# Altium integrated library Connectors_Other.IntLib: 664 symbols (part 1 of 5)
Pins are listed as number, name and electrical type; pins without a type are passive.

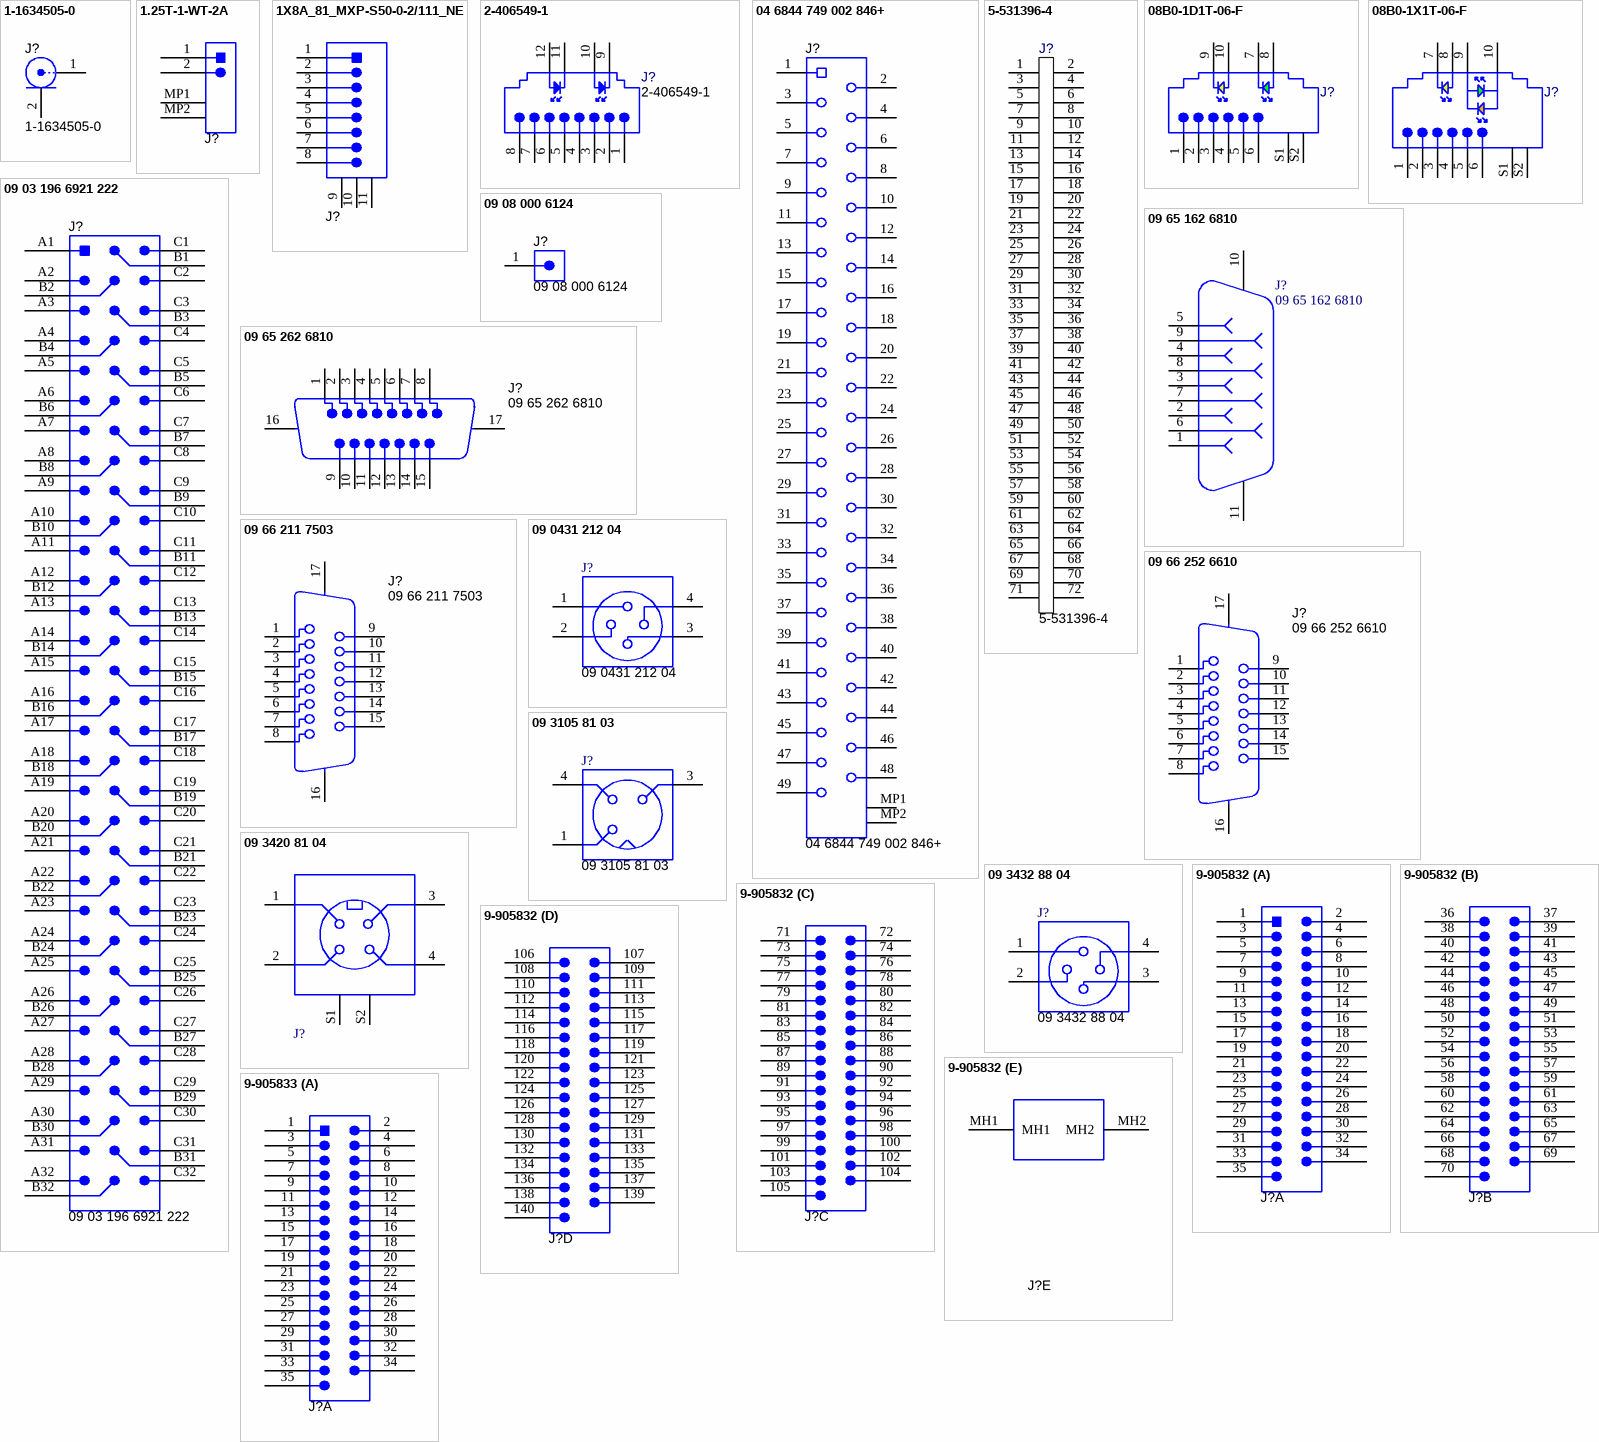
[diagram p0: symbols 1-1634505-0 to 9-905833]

## 1-1634505-0
designator J?
Conn Socket BNC straight 50 ohm PCB mount; Manufacturer: AMP; SymbolCreator: a0412235; Note: STEP model shows options mounting posts
footprint 1-1634505-0
pins: 1, 2

## 1.25T-1-WT-2A
designator J?  (value not drawn)
Header(shrouded), 1.25mm, 2x1, R/A, SMD; Manufacturer: Jhejiang Jinda Electronics; SymbolCreator: Altium; Pitch_mm: 1.25; Gender: Male; Shrouded: Y; Row_Count: 1; ContactFinish: Phosphor bronze; Voltage_V: 125
footprint Jinda_1_25T-1-WT-2A
pins: 1, 2, MP1, MP2

## 1X8A_81_MXP-S50-0-2/111_NE
designator J?  (value not drawn)
Straight PCB plug Pin-in-hole/SMT; Manufacturer: Huber+Suhner; SymbolCreator: a0411947; Green_Lifecycle: Not Set; Green_REACh: Incomplete
footprint H+S_1x8A_81_MXP-S50-0-2_111N
pins: 1, 2, 3, 4, 5, 6, 7, 8, 9, 10, 11

## 2-406549-1
designator J?
RJ45, Right Angle, Yellow/Green LED, tab up; Manufacturer: AMP; SymbolCreator: codlsc
footprint 2-406549-1
pins: 1, 2, 3, 4, 5, 6, 7, 8, 9 K1, 10 A1, 11 K2, 12 A2

## 04 6844 749 002 846+
designator J?
FPC Connector, 0.3mm, 49 Pos, R/A, SMT; Manufacturer: Kyocera; SymbolCreator: Altium; CompType: FFC or FPC; Pitch_mm: 0.3; Gender: Female; Row_Count: 1; Current_A: 0.2; Voltage_V: 50
footprint Kyocera_04_6844_749_002_846+
pins: 1, 2, 3, 4, 5, 6, 7, 8, 9, 10, 11, 12, 13, 14, 15, 16, 17, 18, 19, 20, 21, 22, 23, 24, 25, 26, 27, 28, 29, 30, 31, 32, 33, 34, 35, 36, 37, 38, 39, 40, 41, 42, 43, 44, 45, 46, 47, 48, 49, MP1, MP2

## 5-531396-4
designator J?
Right Angle ZIF connector - OBSOLETE; Manufacturer: AMP; SymbolCreator: codlsc; U/M: EA
footprint 5-531396-4
pins: 1, 2, 3, 4, 5, 6, 7, 8, 9, 10, 11, 12, 13, 14, 15, 16, 17, 18, 19, 20, 21, 22, 23, 24, 25, 26, 27, 28, 29, 30, 31, 32, 33, 34, 35, 36, 37, 38, 39, 40, 41, 42, 43, 44, 45, 46, 47, 48, 49, 50, 51, 52, 53, 54, 55, 56, 57, 58, 59, 60, 61, 62, 63, 64, 65, 66, 67, 68, 69, 70, 71, 72

## 08B0-1D1T-06-F
designator J?  (value not drawn)
Connector, RJ45, R/A, TH; Manufacturer: Bel Fuse; SymbolCreator: Altium; Pitch_mm: 2.03; Gender: Female; Row_Count: 2; RowSpacing_mm: 2.47; ContactFinish: Gold; Cert_UL: Y
footprint Bel_08B0-1D1T-06-F
pins: 1, 2, 3, 4, 5, 6, 7 K1, 8 A1, 9 K2, 10 A2, S1 SHIELD1, S2 SHIELD2

## 08B0-1X1T-06-F
designator J?  (value not drawn)
Connector, RJ45, R/A, TH; Manufacturer: Bel Fuse; SymbolCreator: Altium; Pitch_mm: 2.03; Gender: Female; Row_Count: 2; RowSpacing_mm: 2.47; ContactFinish: Gold; Cert_UL: Y
footprint Bel_08B0-1X1T-06-F
pins: 1, 2, 3, 4, 5, 6, 7 K1, 8 A1, 9 K2, 10 A2, S1 SHIELD1, S2 SHIELD2

## 09 03 196 6921 222
designator J?
Header, 2.54mm, 32x3, R/A, TH; Manufacturer: Harting; SymbolCreator: Altium; Pitch_mm: 2.54; Gender: Male; Shrouded: Y; Row_Count: 3
footprint Harting_09_03_196_6921_222
pins: A1, A2, A3 A2, A4 A3, A5 A3, A6 A4, A7 A4, A8 A5, A9 A5, A10 A6, A11 A6, A12 A7, A13 A7, A14 A8, A15 A8, A16 A9, A17 A9, A18 A10, A19 A10, A20 A11, A21 A11, A22 A12, A23 A12, A24 A13, A25 A13, A26 A14, A27 A14, A28 A15, A29 A15, A30 A16, A31 A16, A32 A17, B1, B2, B3 B2, B4 B3, B5 B3, B6 B4, B7 B4, B8 B5, B9 B5, B10 B6, B11 B6, B12 B7, B13 B7, B14 B8, B15 B8, B16 B9, B17 B9, B18 B10, B19 B10, B20 B11, B21 B11, B22 B12, B23 B12, B24 B13, B25 B13, B26 B14, B27 B14, B28 B15, B29 B15, B30 B16, B31 B16, B32 B17, C1, C2, C3 C2, C4 C3, C5 C3, C6 C4, C7 C4, C8 C5, C9 C5, C10 C6, C11 C6, C12 C7, C13 C7, C14 C8, C15 C8, C16 C9, C17 C9, C18 C10, C19 C10, C20 C11, C21 C11, C22 C12, C23 C12, C24 C13, C25 C13, C26 C14, C27 C14, C28 C15, C29 C15, C30 C16, C31 C16, C32 C17

## 09 08 000 6124
designator J?
Power Connector, 8AWG, SILVER W/PIN, TH; Manufacturer: Harting; SymbolCreator: a0412235
footprint Han-FastLock_09080006124
pins: 1

## 09 65 162 6810
designator J?
D-Sub-9, 11Pos, Male, TH; Manufacturer: Harting; SymbolCreator: x0208326; CompType: D-Sub
footprint Harting_09 65 162 6810
pins: 1, 2, 3, 4, 5, 6, 7, 8, 9, 10, 11

## 09 65 262 6810
designator J?
D-Sub-15, 17Pos, TH; Manufacturer: Harting; SymbolCreator: x0208325; CompType: D-Sub; Gender: Male
footprint Harting_09 65 262 6810
pins: 1, 2, 3, 4, 5, 6, 7, 8, 9, 10, 11, 12, 13, 14, 15, 16 MH1, 17 MH2

## 09 66 211 7503
designator J?
D-Sub-15, 17Pos, TH; Manufacturer: Harting; SymbolCreator: x0208325; CompType: D-Sub; Gender: Female
footprint Harting_09 66 211 7503
pins: 1, 2, 3, 4, 5, 6, 7, 8, 9, 10, 11, 12, 13, 14, 15, 16 MH1, 17 MH2

## 09 66 252 6610
designator J?
D-Sub-15, 17Pos, TH; Manufacturer: Harting; SymbolCreator: x0208325; CompType: D-Sub; Gender: Female
footprint Harting_09 66 252 6610
pins: 1, 2, 3, 4, 5, 6, 7, 8, 9, 10, 11, 12, 13, 14, 15, 16 MH1, 17 MH2

## 09 0431 212 04
designator J?
M12 Socket, 4Pos, TH; Manufacturer: Binder-Connector; SymbolCreator: x0208325
footprint Binder_713_763
footprint Binder_713_763_Edge_ENGR-ONLY
pins: 1, 2  , 3  , 4  

## 09 3105 81 03
designator J?
M5 Socket, 3Pos, Edge Mount; Manufacturer: Binder-Connector; SymbolCreator: Altium
footprint Binder_707_Edge_ENGR-ONLY
pins: 1, 3, 4

## 09 3420 81 04
designator J?  (value not drawn)
M8 Socket, 4Pos, Gold, TH; Manufacturer: Binder-Connector; SymbolCreator: Altium; Gender: Female; Current_A: 4; Voltage_V: 60; Cert_UL: Y
footprint Binder_09_3420_81_04
pins: 1, 2  , 3, 4  , S1, S2

## 09 3432 88 04
designator J?
M12-A Socket, 4Pos, TH; Manufacturer: Binder-Connector; SymbolCreator: x0208325; Gender: Female; Row_Count: 2; ContactFinish: Gold; Current_A: 4; Voltage_V: 250
footprint Binder_09_3432_88_04
footprint Binder_09_3432_88_04_Edge_ENG
pins: 1, 2  , 3  , 4  

## 9-905832
designator J?  (value not drawn)
Header(shrouded), 1.27mm, 140 Pos, TH; Manufacturer: Joy Signal Technology; SymbolCreator: Altium; Pitch_mm: 2.54; Gender: Male; Shrouded: Y; Row_Count: 8; RowSpacing_mm: 1.27; Current_A: 1.7
footprint Joysignal_9-905832
part A pins: 1, 2, 3, 4, 5, 6, 7, 8, 9, 10, 11, 12, 13, 14, 15, 16, 17, 18, 19, 20, 21, 22, 23, 24, 25, 26, 27, 28, 29, 30, 31, 32, 33, 34, 35
part B pins: 36, 37, 38, 39, 40, 41, 42, 43, 44, 45, 46, 47, 48, 49, 50, 51, 52, 53, 54, 55, 56, 57, 58, 59, 60, 61, 62, 63, 64, 65, 66, 67, 68, 69, 70
part C pins: 71, 72, 73, 74, 75, 76, 77, 78, 79, 80, 81, 82, 83, 84, 85, 86, 87, 88, 89, 90, 91, 92, 93, 94, 95, 96, 97, 98, 99, 100, 101, 102, 103, 104, 105
part D pins: 106, 107, 108, 109, 110, 111, 112, 113, 114, 115, 116, 117, 118, 119, 120, 121, 122, 123, 124, 125, 126, 127, 128, 129, 130, 131, 132, 133, 134, 135, 136, 137, 138, 139, 140
part E pins: MH1, MH2

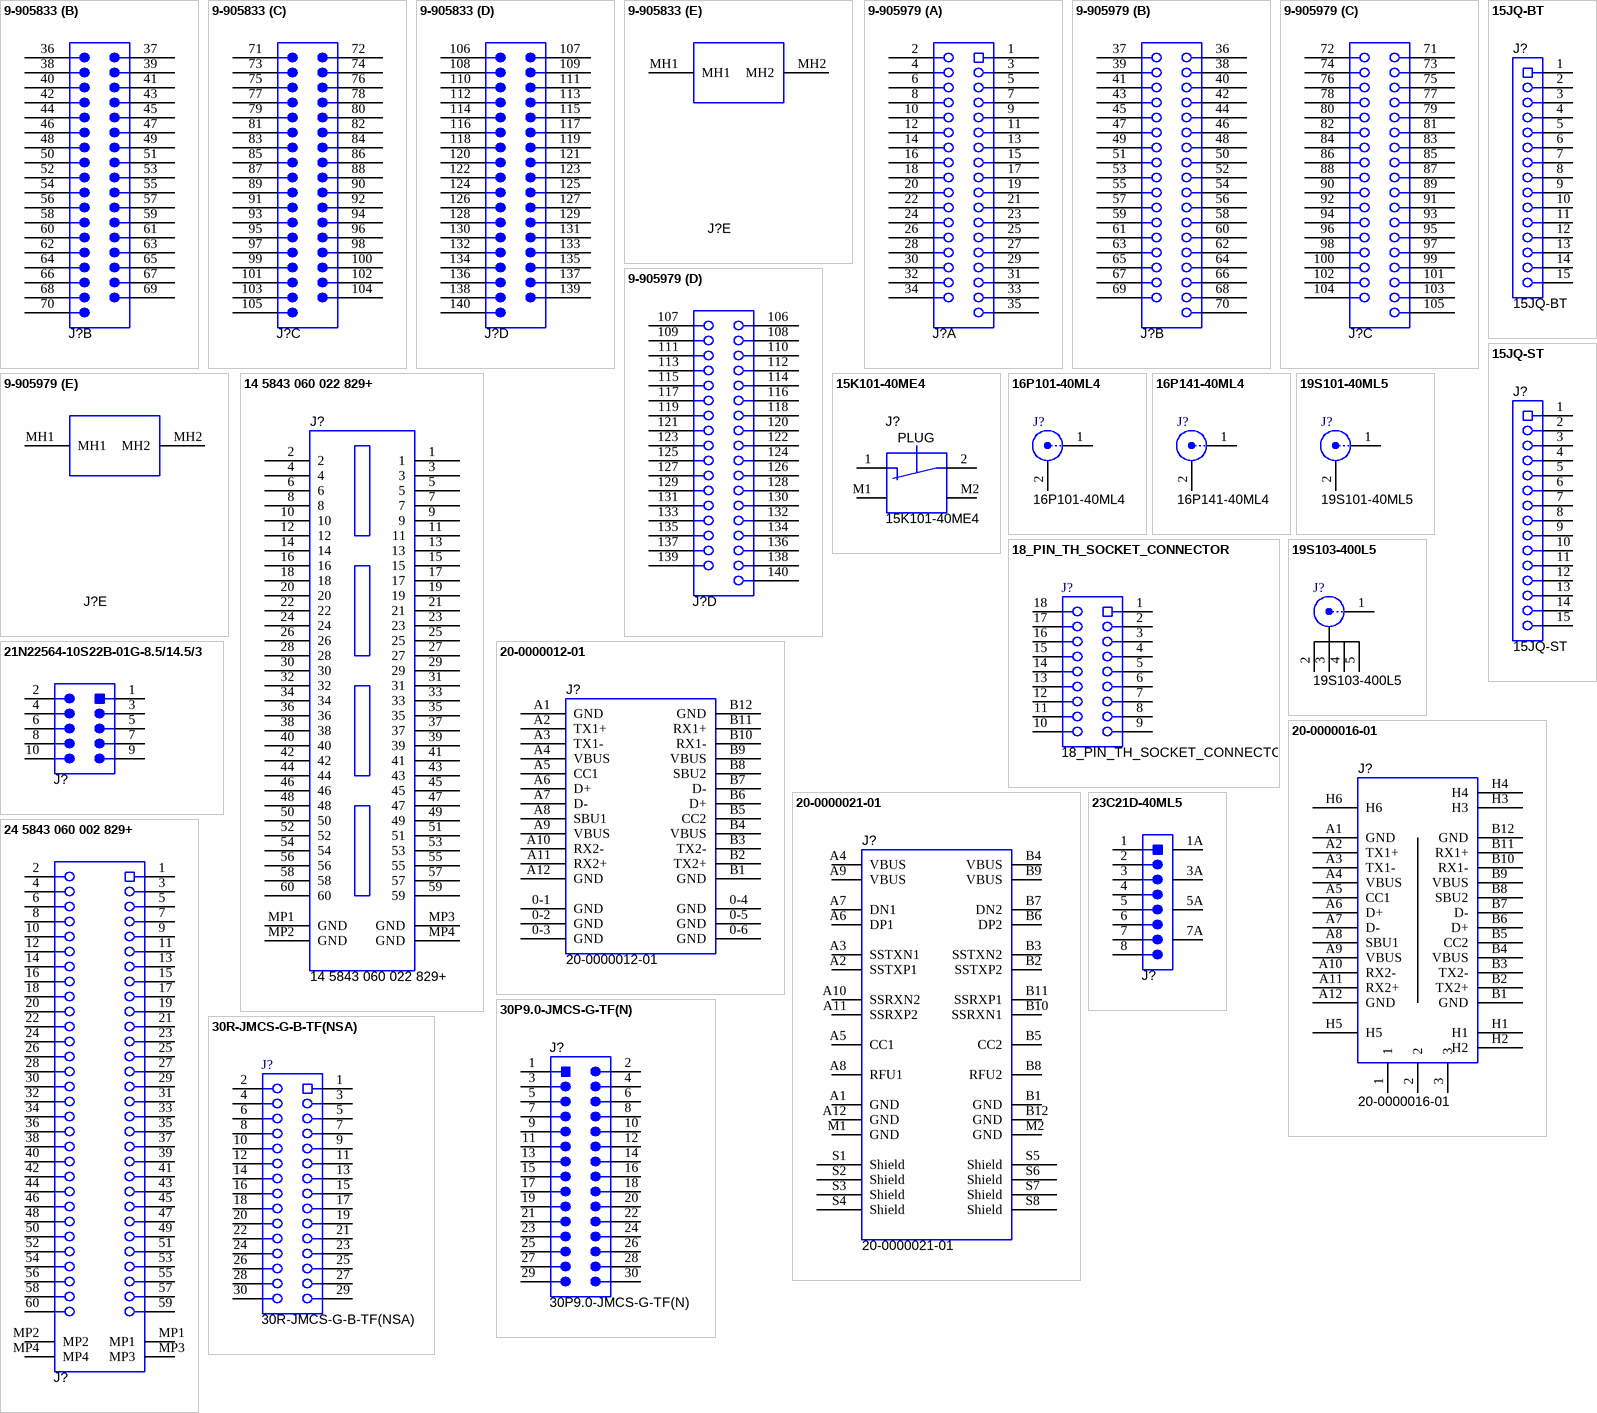
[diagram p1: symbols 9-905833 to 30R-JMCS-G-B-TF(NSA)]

## 9-905833
designator J?  (value not drawn)
Header(shrouded), 1.27mm, 140 Pos, R/A, TH; Manufacturer: Joy Signal Technology; SymbolCreator: Altium; Pitch_mm: 2.54; Gender: Male; Shrouded: Y; Row_Count: 8; RowSpacing_mm: 1.27; Current_A: 1.7
footprint Joysignal_9-905833
part A pins: 1, 2, 3, 4, 5, 6, 7, 8, 9, 10, 11, 12, 13, 14, 15, 16, 17, 18, 19, 20, 21, 22, 23, 24, 25, 26, 27, 28, 29, 30, 31, 32, 33, 34, 35
part B pins: 36, 37, 38, 39, 40, 41, 42, 43, 44, 45, 46, 47, 48, 49, 50, 51, 52, 53, 54, 55, 56, 57, 58, 59, 60, 61, 62, 63, 64, 65, 66, 67, 68, 69, 70
part C pins: 71, 72, 73, 74, 75, 76, 77, 78, 79, 80, 81, 82, 83, 84, 85, 86, 87, 88, 89, 90, 91, 92, 93, 94, 95, 96, 97, 98, 99, 100, 101, 102, 103, 104, 105
part D pins: 106, 107, 108, 109, 110, 111, 112, 113, 114, 115, 116, 117, 118, 119, 120, 121, 122, 123, 124, 125, 126, 127, 128, 129, 130, 131, 132, 133, 134, 135, 136, 137, 138, 139, 140
part E pins: MH1, MH2

## 9-905979
designator J?  (value not drawn)
Receptacle, 1.27mm, 140 Pos, R/A, TH; Manufacturer: Joy Signal Technology; SymbolCreator: Altium; Pitch_mm: 2.54; Gender: Female; Row_Count: 8; RowSpacing_mm: 1.27; Current_A: 1.7
footprint Joysignal_9-905979
part A pins: 1, 2, 3, 4, 5, 6, 7, 8, 9, 10, 11, 12, 13, 14, 15, 16, 17, 18, 19, 20, 21, 22, 23, 24, 25, 26, 27, 28, 29, 30, 31, 32, 33, 34, 35
part B pins: 36, 37, 38, 39, 40, 41, 42, 43, 44, 45, 46, 47, 48, 49, 50, 51, 52, 53, 54, 55, 56, 57, 58, 59, 60, 61, 62, 63, 64, 65, 66, 67, 68, 69, 70
part C pins: 71, 72, 73, 74, 75, 76, 77, 78, 79, 80, 81, 82, 83, 84, 85, 86, 87, 88, 89, 90, 91, 92, 93, 94, 95, 96, 97, 98, 99, 100, 101, 102, 103, 104, 105
part D pins: 106, 107, 108, 109, 110, 111, 112, 113, 114, 115, 116, 117, 118, 119, 120, 121, 122, 123, 124, 125, 126, 127, 128, 129, 130, 131, 132, 133, 134, 135, 136, 137, 138, 139, 140
part E pins: MH1, MH2

## 14 5843 060 022 829+
designator J?
Header, 0.35mm, 30x2, SMT; Manufacturer: Kyocera; SymbolCreator: Altium; Pitch_mm: 0.35; Gender: Male; Row_Count: 2; Current_A: 0.3; Voltage_V: 60
footprint Kyocera_14_5843_060_022_829+
pins: 1, 2, 3, 4, 5, 6, 7, 8, 9, 10, 11, 12, 13, 14, 15, 16, 17, 18, 19, 20, 21, 22, 23, 24, 25, 26, 27, 28, 29, 30, 31, 32, 33, 34, 35, 36, 37, 38, 39, 40, 41, 42, 43, 44, 45, 46, 47, 48, 49, 50, 51, 52, 53, 54, 55, 56, 57, 58, 59, 60, MP1 GND, MP2 GND, MP3 GND, MP4 GND
1 alternate drawing of the same symbol

## 15JQ-BT
designator J?
Receptacle, 2.5 mm, 15x1, TH; Manufacturer: JST Manufacturing; SymbolCreator: Altium
footprint JST_15JQ-BT
pins: 1, 2, 3, 4, 5, 6, 7, 8, 9, 10, 11, 12, 13, 14, 15

## 15JQ-ST
designator J?
Receptacle, 2.5 mm, 15x1, R/A, TH; Manufacturer: JST Manufacturing; SymbolCreator: Altium
footprint JST_15JQ-ST
pins: 1, 2, 3, 4, 5, 6, 7, 8, 9, 10, 11, 12, 13, 14, 15

## 15K101-40ME4
designator J?
RF Test Switch, SMD; Manufacturer: Rosenberger; SymbolCreator: x0208326
footprint Rosenberger_15K101-40ME4
pins: 1 "NC", 2 (power) "COM", M1, M2

## 16P101-40ML4
designator J?
FMC, Straight Jack, SMT; Manufacturer: Rosenberger; SymbolCreator: a0799628
footprint Rosenberger_16P101-40ML4
footprint Rosenberger_16P101-40ML4_NO-VIAS
pins: 1, 2

## 16P141-40ML4
designator J?
FMC, Straight Jack, SMT; Manufacturer: Rosenberger; SymbolCreator: a0799628
footprint Rosenberger_16P141-40ML4
footprint Rosenberger_16P141-40ML4_NO-VIAS
pins: 1, 2

## 18_PIN_TH_SOCKET_CONNECTOR
designator J?
18_PIN_TH_SOCKET_CONNECTOR, TH; Manufacturer: Texas Instruments; SymbolVersion: 20150930; SymbolCreator: Altium
footprint TI_18_PIN_TH_SOCKET_CONNECTOR
pins: 1, 2, 3, 4, 5, 6, 7, 8, 9, 10, 11, 12, 13, 14, 15, 16, 17, 18

## 19S101-40ML5
designator J?
Connector, RF 50 Ohms, SMT; Manufacturer: Rosenberger; SymbolCreator: a0799628
footprint 19S101_40ML5
pins: 1, 2

## 19S103-400L5
designator J?
Straight Plug, 50 Ohms, Gold, TH; Manufacturer: Rosenberger; SymbolCreator: a0799628; Gender: Male; Shrouded: N; Current_A: 1.2; Voltage_V: 335
footprint Rosenberger_19S103-400L5
pins: 1, 2, 3, 4, 5

## 20-0000012-01
designator J?
Connector, Plug, USB Type C, Edge Mount; Manufacturer: Lintes Technology; SymbolCreator: Altium; Gender: Female
footprint Lintes_20-0000012-01
pins: 0-1 GND, 0-2 GND, 0-3 GND, 0-4 GND, 0-5 GND, 0-6 GND, A1 GND, A2 TX1+, A3 TX1-, A4 VBUS, A5 CC1, A6 D+, A7 D-, A8 SBU1, A9 VBUS, A10 RX2-, A11 RX2+, A12 GND, B1 GND, B2 TX2+, B3 TX2-, B4 VBUS, B5 CC2, B6 D+, B7 D-, B8 SBU2, B9 VBUS, B10 RX1-, B11 RX1+, B12 GND

## 20-0000016-01
designator J?
Connector, Receptacle, USB Type C, R/A, SMT; Manufacturer: Lintes Technology; SymbolCreator: Altium; Gender: Female; Green_Lifecycle: Not Set; Green_REACh: Incomplete
footprint Lintes_20-0000016-01
pins: 1, 2, 3, A1 GND, A2 TX1+, A3 TX1-, A4 VBUS, A5 CC1, A6 D+, A7 D-, A8 SBU1, A9 VBUS, A10 RX2-, A11 RX2+, A12 GND, B1 GND, B2 TX2+, B3 TX2-, B4 VBUS, B5 CC2, B6 D+, B7 D-, B8 SBU2, B9 VBUS, B10 RX1-, B11 RX1+, B12 GND, H1, H2, H3, H4, H5, H6

## 20-0000021-01
designator J?
Receptacle, USB Type C, 26 Position; Manufacturer: Lintes Technology; SymbolCreator: Altium; Gender: Female; ContactFinish: Gold; Current_A: 3; Voltage_V: 5; Cert_UL: Y
footprint Lintes_20-0000021-01
pins: A1 GND, A2 SSTXP1, A3 SSTXN1, A4 VBUS, A5 CC1, A6 DP1, A7 DN1, A8 RFU1, A9 VBUS, A10 SSRXN2, A11 SSRXP2, A12 GND, B1 GND, B2 SSTXP2, B3 SSTXN2, B4 VBUS, B5 CC2, B6 DP2, B7 DN2, B8 RFU2, B9 VBUS, B10 SSRXN1, B11 SSRXP1, B12 GND, M1 GND, M2 GND, S1 Shield, S2 Shield, S3 Shield, S4 Shield, S5 Shield, S6 Shield, S7 Shield, S8 Shield

## 21N22564-10S22B-01G-8.5/14.5/3
designator J?  (value not drawn)
Header, 2.54mm, 5x2, Gold, TH; Manufacturer: JVE Global; SymbolCreator: Altium; Pitch_mm: 2.54; Gender: Male; Shrouded: N; Row_Count: 2; Current_A: 3; Voltage_V: 230; Cert_UL: Y
footprint JVE_21N22564-10S22B-01G-85-145-3
pins: 1, 2, 3, 4, 5, 6, 7, 8, 9, 10

## 23C21D-40ML5
designator J?  (value not drawn)
Mini-Coax, 8-Channel Block Right Angle; Manufacturer: Rosenberger; SymbolCreator: x0208325
footprint Rosenberger_23C21D-40ML5
pins: 1, 1A, 2, 3, 3A, 4, 5, 5A, 6, 7, 7A, 8

## 24 5843 060 002 829+
designator J?  (value not drawn)
Receptacle, 0.35mm, 30x2, SMT; Manufacturer: Kyocera; SymbolCreator: Altium; Pitch_mm: 0.35; Gender: Female; Row_Count: 2; Current_A: 0.3; Voltage_V: 60
footprint Kyocera_24_5843_060_002_829+
pins: 1, 2, 3, 4, 5, 6, 7, 8, 9, 10, 11, 12, 13, 14, 15, 16, 17, 18, 19, 20, 21, 22, 23, 24, 25, 26, 27, 28, 29, 30, 31, 32, 33, 34, 35, 36, 37, 38, 39, 40, 41, 42, 43, 44, 45, 46, 47, 48, 49, 50, 51, 52, 53, 54, 55, 56, 57, 58, 59, 60, MP1, MP2, MP3, MP4

## 30P9.0-JMCS-G-TF(N)
designator J?
Plug, 0.5mm, 15x2, SMD; Manufacturer: JST Manufacturing; SymbolCreator: a0412235
footprint JST_30P9_0-JMCS-G-TF
pins: 1, 2, 3, 4, 5, 6, 7, 8, 9, 10, 11, 12, 13, 14, 15, 16, 17, 18, 19, 20, 21, 22, 23, 24, 25, 26, 27, 28, 29, 30

## 30R-JMCS-G-B-TF(NSA)
designator J?
Receptacle, 0.5mm, 15x2, SMD; Manufacturer: JST Manufacturing; SymbolCreator: a0412235
footprint JST_30R-JMCS-G-B-TF
pins: 1, 2, 3, 4, 5, 6, 7, 8, 9, 10, 11, 12, 13, 14, 15, 16, 17, 18, 19, 20, 21, 22, 23, 24, 25, 26, 27, 28, 29, 30

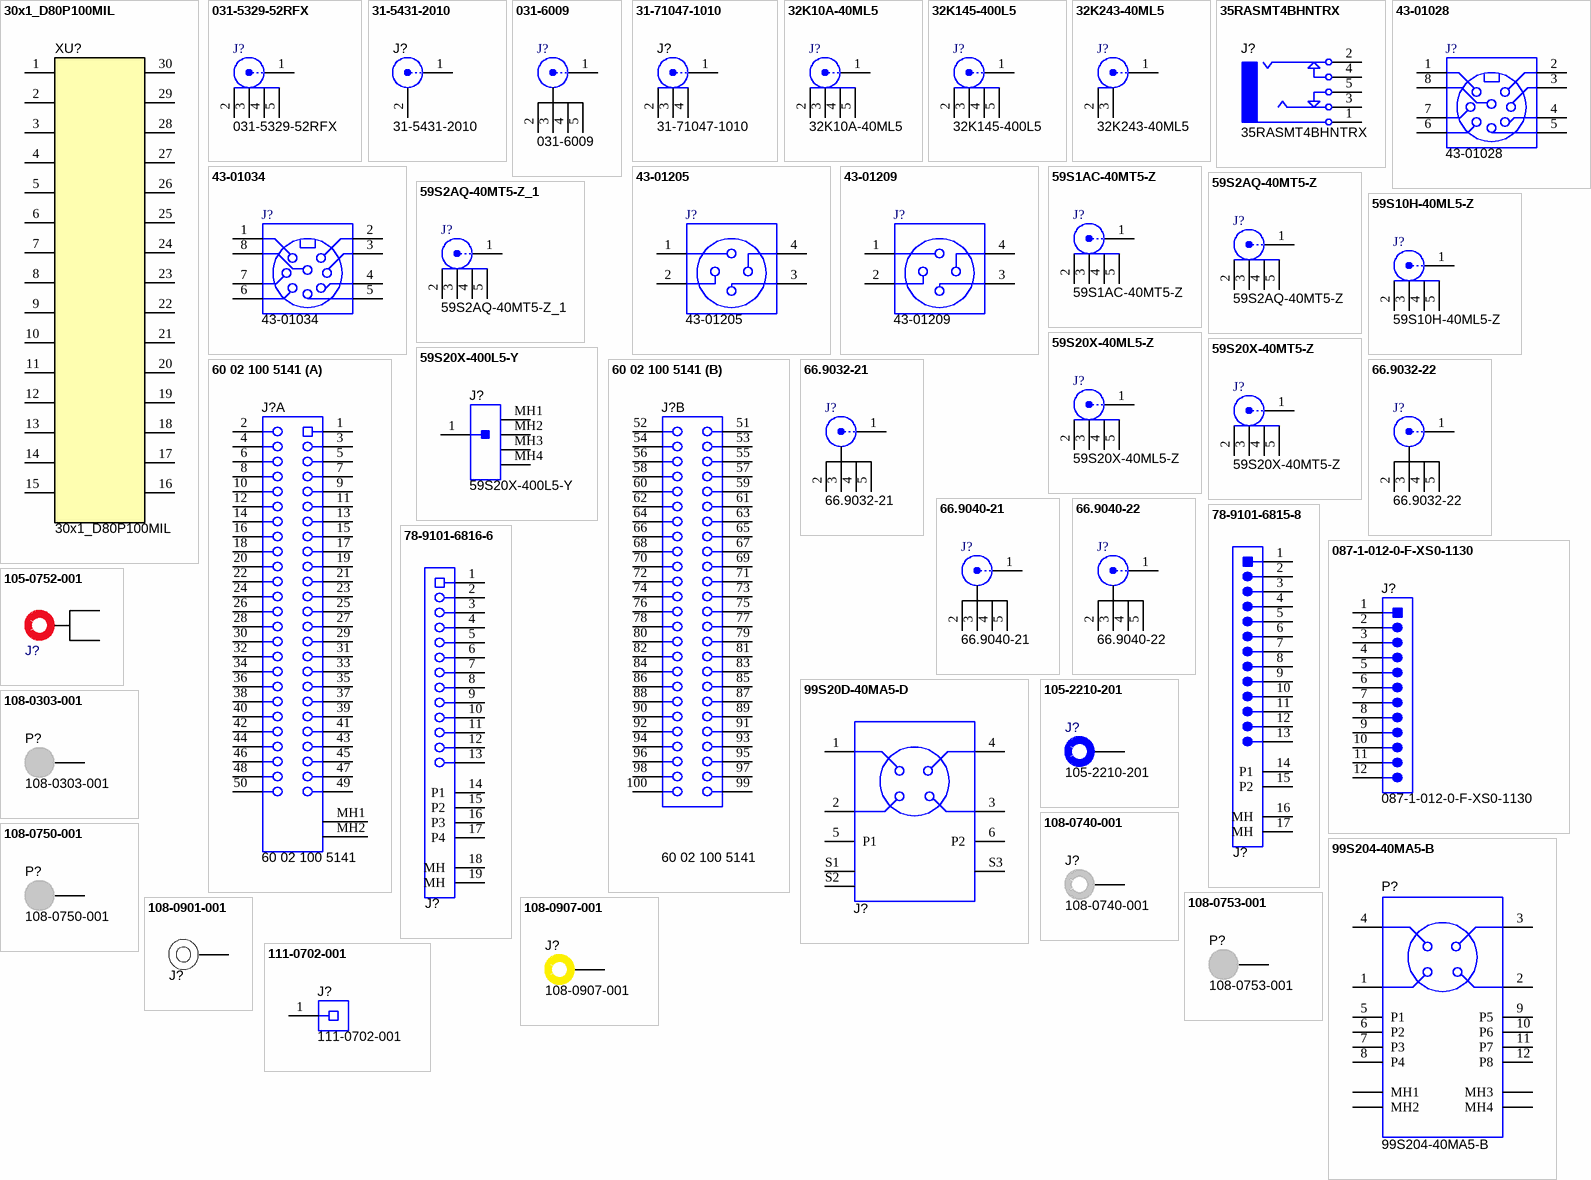
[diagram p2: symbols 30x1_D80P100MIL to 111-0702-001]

## 30x1_D80P100MIL
designator XU?
Footprint for pogo-pins, 100mil, 30x1, SMT; Manufacturer: Any; SymbolCreator: Altium; CompType: Connector; Pitch_mm: 2.54; Row_Count: 1
footprint TI-30x1_D80P100MIL
pins: 1, 2, 3, 4, 5, 6, 7, 8, 9, 10, 11, 12, 13, 14, 15, 16, 17, 18, 19, 20, 21, 22, 23, 24, 25, 26, 27, 28, 29, 30

## 031-5329-52RFX
designator J?
BNC Receptacle, 50 Ohm, TH; Manufacturer: Amphenol RF; SymbolCreator: X0208326; Gender: Female; ContactFinish: Gold; Voltage_V: 500
footprint Amphenol_031-5329-52RFX
pins: 1, 2, 3, 4, 5

## 31-5431-2010
designator J?
Connector, BNC Jack, 1 Position, R/A, TH; Manufacturer: Amphenol-Tuchel Electronics; SymbolCreator: Altium; Gender: Female; ContactFinish: Gold
footprint Amphenol_31-5431-2010
pins: 1, 2

## 031-6009
designator J?
75 Ohm BNC Edge Mount Receptacle, RF Connector, RoHS, SMT; Manufacturer: Amphenol RF; SymbolCreator: a0799628
footprint Amphenol_031-6009
pins: 1, 2, 3, 4, 5

## 31-71047-1010
designator J?
Connector, BNC, 75 ohm, Isolated, R/A, TH; Manufacturer: Amphenol RF; SymbolCreator: a0411947; Green_Lifecycle: Not Set; Green_REACh: Incomplete
footprint CONN_31-71047-1010
pins: 1, 2, 3, 4

## 32K10A-40ML5
designator J?
SMA, Straight Jack, SMT; Manufacturer: Rosenberger; SymbolCreator: X0208326
footprint Rosenberger_32K10A-40ML5
pins: 1, 2, 3, 4, 5

## 32K145-400L5
designator J?
SMA, Straight Jack, SMT; Manufacturer: Rosenberger; SymbolCreator: X0208326
footprint Rosenberger_32K145-400L5
footprint 32K145-400_FR4_130_ML_MS_SB
pins: 1, 2, 3, 4, 5

## 32K243-40ML5
designator J?
SMA JACK 50 OHM, R/A, SMT; Manufacturer: Rosenberger; SymbolCreator: a0412235; Gender: Male; ContactFinish: Gold; Voltage_V: 480; Green_Lifecycle: Not Set; Green_REACh: Incomplete
footprint Rosenberger_32K243-40ML5
pins: 1, 2, 3

## 35RASMT4BHNTRX
designator J?
Audio Jack, 3.5mm, Stereo, R/A, SMT; Manufacturer: Switchcraft; SymbolCreator: x0208326; CompType: Audio Connector
footprint Switchcraft_35RASM
pins: 1 SLEEVE, 2 RING, 3 TIP, 4 RING SWITCH, 5 TIP SWITCH

## 43-01028
designator J?
M12 Socket, 8Pos, TH; Manufacturer: Conec; SymbolCreator: x0208326
footprint Conec_43-01028
pins: 1, 2  , 3  , 4, 5, 6  , 7  , 8

## 43-01034
designator J?
M12 Socket, 8Pos, TH; Manufacturer: Conec; SymbolCreator: x0208326
footprint Conec_43-01034
pins: 1, 2  , 3  , 4, 5, 6  , 7  , 8

## 43-01205
designator J?
M12 Socket, Backmounting, 4Pos, Gold, R/A, TH; Manufacturer: Conec; SymbolCreator: x0208325
footprint Conec_43-01205
pins: 1, 2  , 3  , 4  

## 43-01209
designator J?
M12 Socket, Frontmounting, 4Pos, Gold, R/A, TH; Manufacturer: Conec; SymbolCreator: x0208325
footprint Conec_43-01209
pins: 1, 2  , 3  , 4  

## 59S1AC-40MT5-Z
designator J?
Connector, HF, 50 Ohm, TH; Manufacturer: Rosenberger; SymbolCreator: X0208326; Pitch_mm: 5.08; Gender: Male; ContactFinish: Tin; Current_A: 1; Voltage_V: 335
footprint Rosenberger_59S1AC-40MT5-Z
pins: 1, 2, 3, 4, 5

## 59S2AQ-40MT5-Z
designator J?
Connector. RF 50 Ohm R/A, TH; Manufacturer: Rosenberger; SymbolCreator: X0208326; CompType: Right Angle Plug
footprint Rosenberger_59S2AQ-40MT5
pins: 1, 2, 3, 4, 5

## 59S2AQ-40MT5-Z_1
designator J?
Connector, HF, 50 Ohm, TH; Manufacturer: Rosenberger; SymbolCreator: X0208326; Gender: Male; ContactFinish: Gold; Current_A: 1; Voltage_V: 335
footprint Rosenberger_59S2AQ-40MT5-Z_1
footprint Rosenberger_59S2AQ-40MT5-Z_1_Alternate
pins: 1, 2, 3, 4, 5

## 59S10H-40ML5-Z
designator J?
Connector, HF, 50 Ohm, TH; Manufacturer: Rosenberger; SymbolCreator: X0208326; Gender: Male; ContactFinish: Gold; Green_Lifecycle: Not Set; Green_REACh: Incomplete
footprint Rosenberger_59S10H-40ML5-Z
pins: 1, 2, 3, 4, 5

## 59S20X-40ML5-Z
designator J?
Connector, RF, 50 Ohm, R/A, TH; Manufacturer: Rosenberger; SymbolCreator: X0208326
footprint Rosenberger_59S20X-40ML5-Z
pins: 1, 2, 3, 4, 5

## 59S20X-40MT5-Z
designator J?
Connector. RF 50 Ohm R/A, TH; Manufacturer: Rosenberger; SymbolCreator: X0208326
footprint Rosenberger_59S20X-40MT5-Z
pins: 1, 2, 3, 4, 5

## 59S20X-400L5-Y
designator J?
RIGHT ANGLE PLUG FOR PCB; Manufacturer: Rosenberger; SymbolCreator: x0208325
footprint Rosenberger_59S20X-400L5
pins: 1, MH1, MH2, MH3, MH4

## 60 02 100 5141
designator J?
Receptacle, SCSI, 100 pin, R/A, TH; Manufacturer: Harting; SymbolCreator: x0208325
footprint Harting_60 02 100 5141
part A pins: 1, 2, 3, 4, 5, 6, 7, 8, 9, 10, 11, 12, 13, 14, 15, 16, 17, 18, 19, 20, 21, 22, 23, 24, 25, 26, 27, 28, 29, 30, 31, 32, 33, 34, 35, 36, 37, 38, 39, 40, 41, 42, 43, 44, 45, 46, 47, 48, 49, 50, MH1 51, MH2 52
part B pins: 51, 52, 53, 54, 55, 56, 57, 58, 59, 60, 61, 62, 63, 64, 65, 66, 67, 68, 69, 70, 71, 72, 73, 74, 75, 76, 77, 78, 79, 80, 81, 82, 83, 84, 85, 86, 87, 88, 89, 90, 91, 92, 93, 94, 95, 96, 97, 98, 99, 100

## 66.9032-21
designator J?
Connector, XELA-4, Black, TH; Manufacturer: Multi-Contact; SymbolCreator: a0799628
footprint Multi-Contact_66_9032-21
pins: 1, 2, 3, 4, 5

## 66.9032-22
designator J?
Connector, XELA-4, Red, TH; Manufacturer: Multi-Contact; SymbolCreator: a0799628
footprint Multi-Contact_66_9032-22
pins: 1, 2, 3, 4, 5

## 66.9040-21
designator J?
MAH561 Connector, XELW-4, Black, THD; Manufacturer: Multi-Contact; SymbolCreator: a0799628
footprint Multi-Contact_66_9040-21
pins: 1, 2, 3, 4, 5

## 66.9040-22
designator J?
MAH561 Connector, XELW-4, Red, THD; Manufacturer: Multi-Contact; SymbolCreator: a0799628
footprint Multi-Contact_66_9040-22
pins: 1, 2, 3, 4, 5

## 78-9101-6815-8
designator J?  (value not drawn)
Header, I/O Module, 2mm, 13x1 Signal, 2x2 Power, R/A, Black, Gold, SMT, NDA Restrictions; Manufacturer: 3M; SymbolCreator: Altium; CompType: Connector; Pitch_mm: 2; Gender: Male; Cert_UL: Y
footprint 3M_78-9101-6815-8
pins: 1, 2, 3, 4, 5, 6, 7, 8, 9, 10, 11, 12, 13, 14 P1 (power), 15 P2 (power), 16 MH (power), 17 MH (power)

## 78-9101-6816-6
designator J?  (value not drawn)
Receptacle, I/O Module, 2mm, 13x1 Signal, 4x2 Power, R/A, Black, Gold, SMT, NDA Restrictions; Manufacturer: 3M; SymbolCreator: Altium; Pitch_mm: 2; Gender: Female; Cert_UL: Y
footprint 3M_78-9101-6816-6
pins: 1, 2, 3, 4, 5, 6, 7, 8, 9, 10, 11, 12, 13, 14 P1 (power), 15 P2 (power), 16 P3 (power), 17 P4 (power), 18 MH (power), 19 MH (power)

## 087-1-012-0-F-XS0-1130
designator J?
Header, 2.54 mm, 12x1, Au, TH; Manufacturer: MPE-Garry GmbH; SymbolCreator: a0412235
footprint MPE_087-1-012-0-F-XS0-1130
pins: 1, 2, 3, 4, 5, 6, 7, 8, 9, 10, 11, 12

## 99S20D-40MA5-D
designator J?  (value not drawn)
RF Coaxial Connector, Bordeaux, R/A, TH; Manufacturer: Rosenberger; SymbolCreator: Altium; CompType: Plug; Gender: Male; Shrouded: Y; ContactFinish: Gold; Voltage_V: 100
footprint Rosenberger_99S20D-40MA5-D
pins: 1, 2, 3, 4, 5 P1, 6 P2, S1, S2, S3

## 99S204-40MA5-B
designator P?
Plug, 12 POS, R/A, Tin, TH; Manufacturer: Rosenberger; SymbolCreator: Altium; Gender: Male; Voltage_V: 100
footprint Rosenberger_99S204-40MA5-B
pins: 1, 2, 3, 4, 5 P1, 6 P2, 7 P3, 8 P4, 9 P5, 10 P6, 11 P7, 12 P8, MH1, MH2, MH3, MH4

## 105-0752-001
designator J?  (value not drawn)
Horizontal Test Jack, TH; Manufacturer: Cinch Connectivity; SymbolCreator: Altiumn; Pitch_mm: 10.16; Gender: Female; Row_Count: 1; ContactFinish: Gold; Current_A: 5; Voltage_V: 2100
footprint Johnson_105-0752-001
pins: 1, 2

## 105-2210-201
designator J?
Banana Jack, Insulated, Blue, TH; Manufacturer: Cinch Connectivity; SymbolCreator: a0411947; Gender: Female; ContactFinish: Silver; Current_A: 5; Voltage_V: 5000
footprint Emerson_105-2210-201
pins: 1

## 108-0303-001
designator P?
Black Banana Plug, Insulated, Round Solder/Solderless Hole, TH; Manufacturer: Cinch Connectivity; SymbolCreator: Altium; CompType: Banana Jack
footprint Emerson_108-0303-001
pins: 1

## 108-0740-001
designator J?
Standard Banana Jack, Uninsulated, 15A; Manufacturer: Cinch Connectivity; SymbolCreator: a0412235; Green_Lifecycle: Active; Green_REACh: Passed
footprint Johnson_108-0740-001
pins: 1

## 108-0750-001
designator P?
Banana Plug, Uninsulated, Nickel, TH; Manufacturer: Cinch Connectivity; SymbolCreator: Altium; CompType: Banana Jack
footprint Emerson_108-0750-001
pins: 1

## 108-0753-001
designator P?
Banana Plug, Uninsulated, Hex Body Threaded Backhole,TH; Manufacturer: Cinch Connectivity; SymbolCreator: Altium; CompType: Banana Jack
footprint Emerson_108-0753-001
pins: 1

## 108-0901-001
designator J?  (value not drawn)
Banana Jack Insul Nylon White, TH; Manufacturer: Cinch Connectivity; SymbolCreator: Altium; Gender: Female; ContactFinish: Tin; Current_A: 15; Green_Lifecycle: Not Set; Green_REACh: Incomplete
footprint Emerson_108-0901-001
pins: 1

## 108-0907-001
designator J?
BANANA JACK, 15A, Insulated, Nylon,Yellow; Manufacturer: Cinch Connectivity; SymbolCreator: a0799721; Green_Lifecycle: Not Set; Green_REACh: Incomplete
footprint CONN_108-0907-001
pins: 1

## 111-0702-001
designator J?
Binding Post, Red, TH; Manufacturer: Cinch Connectivity; SymbolCreator: a0799628; CompType: Receptacle
footprint Emerson_111-0702-001
pins: 1

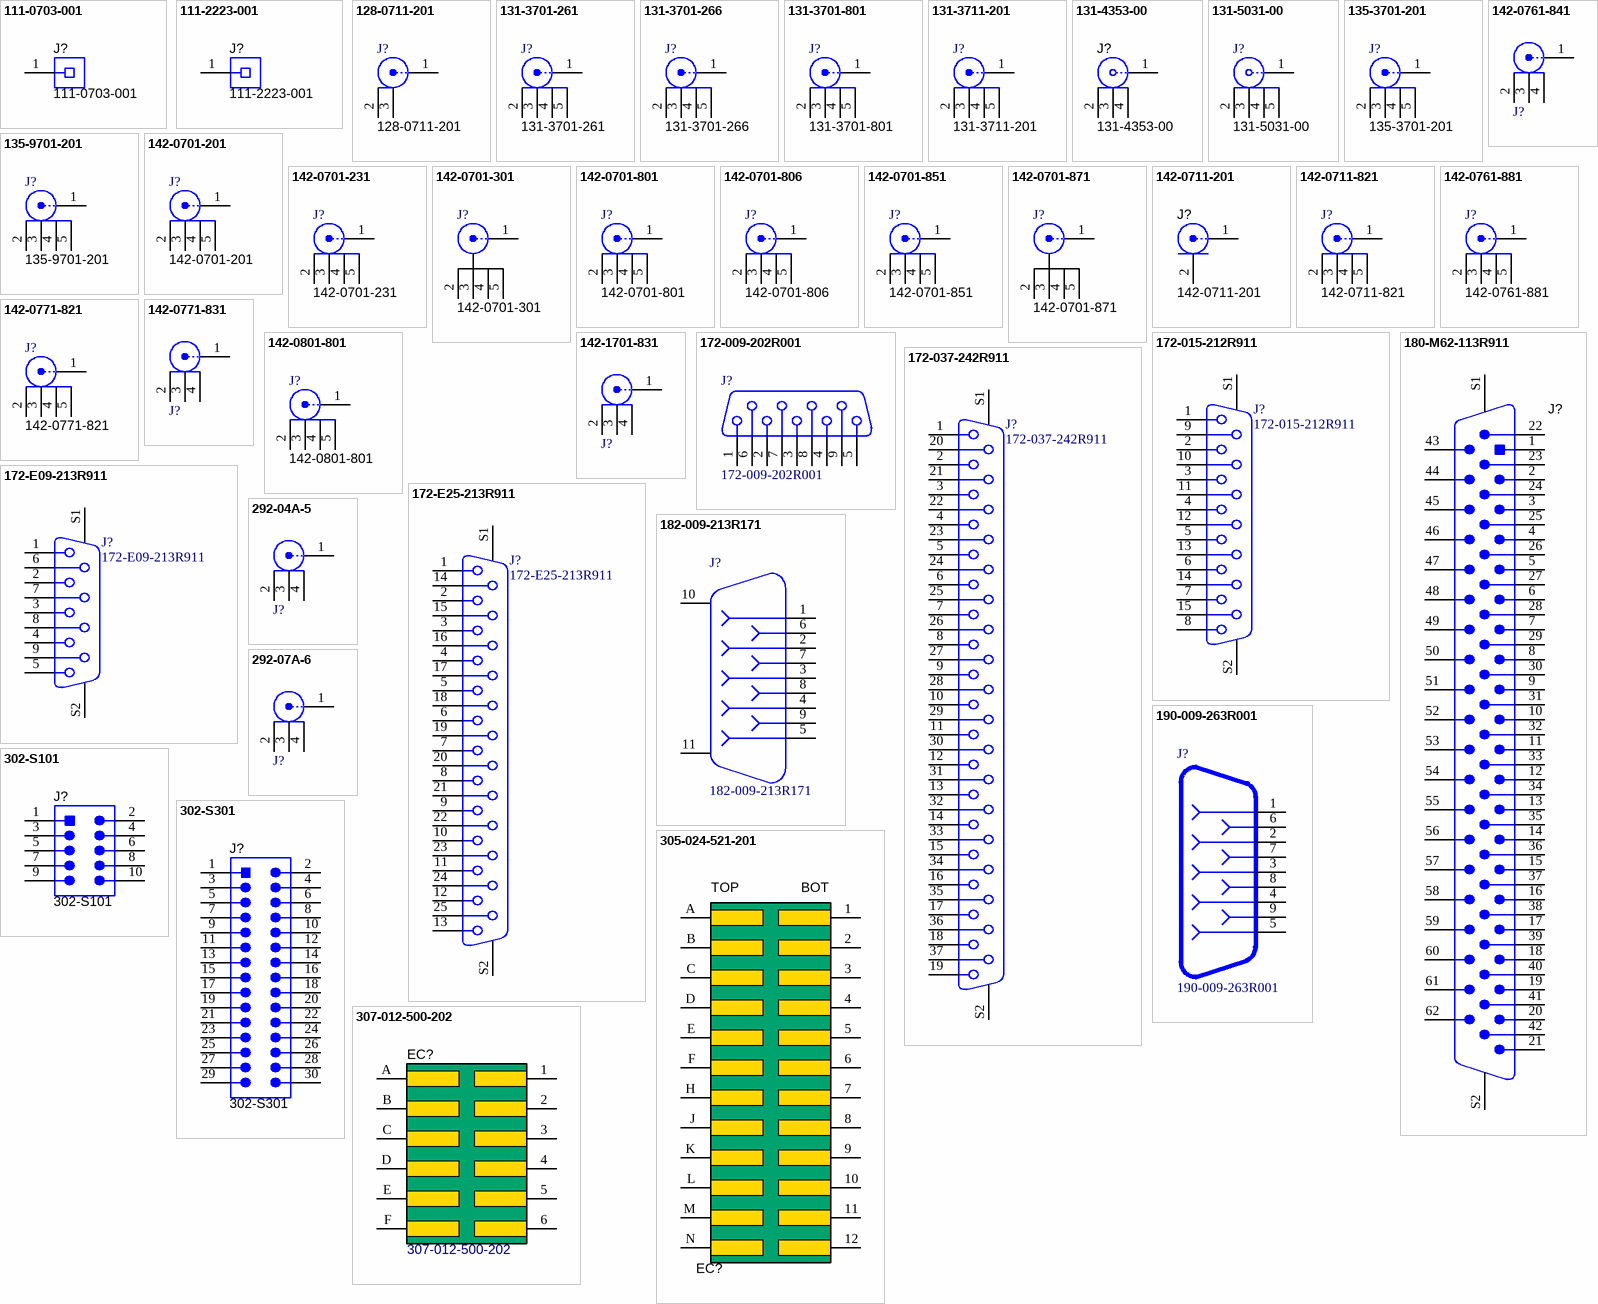
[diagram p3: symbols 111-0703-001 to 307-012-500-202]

## 111-0703-001
designator J?
Binding Post, Black, TH; Manufacturer: Cinch Connectivity; SymbolCreator: a0799628
footprint Emerson_111-0703-001
pins: 1

## 111-2223-001
designator J?
Binding Post, Nickel, TH; Manufacturer: Cinch Connectivity; SymbolCreator: a0799628; CompType: Receptacle; Green_Lifecycle: Not Set; Green_REACh: Incomplete
footprint Emerson_111-2223-001
pins: 1

## 128-0711-201
designator J?
UMC Straight Jack Receptacle, 50 Ohm, Gold, SMT; Manufacturer: Cinch Connectivity; SymbolCreator: a0412235; Gender: Female
footprint Johnson_128-0711-201
pins: 1, 2, 3

## 131-3701-261
designator J?
Connector, SMB,Vertical RCP 0-4GHz, 50 ohm, TH; Manufacturer: Cinch Connectivity; SymbolCreator: X0208326; Green_Lifecycle: Not Set; Green_REACh: Incomplete
footprint CONN_131-3701-261
pins: 1, 2, 3, 4, 5

## 131-3701-266
designator J?
Connector, SMB, Jack, 50 ohm, TH; Manufacturer: Cinch Connectivity; SymbolCreator: X0208326; Pitch_mm: 5.08; Gender: Female; ContactFinish: Gold
footprint CONN_131-3701-261
pins: 1, 2, 3, 4, 5

## 131-3701-801
designator J?
Connector, SMB Jack, End launch, SMT; Manufacturer: Cinch Connectivity; SymbolCreator: X0208326
footprint Emerson_131-3701-801
pins: 1, 2, 3, 4, 5

## 131-3711-201
designator J?
Connector, SMT, SMB Jack Assembly 50 ohm; Manufacturer: Cinch Connectivity; SymbolCreator: X0208326; Gender: Male; ContactFinish: Gold
footprint Johnson_131-3711-201
pins: 1, 2, 3, 4, 5

## 131-4353-00
designator J?
Probe Connector, Receptacle, 1Pos, TH; Manufacturer: Tektronix; SymbolCreator: Altium; Gender: Female; Row_Count: 1; Green_Lifecycle: Not Set; Green_REACh: Incomplete
footprint Tektronix_131-4353-00
pins: 1, 2, 3, 4

## 131-5031-00
designator J?
Compact Probe Tip Circuit Board Test Points, TH, 25 per; Manufacturer: Tektronix; Green_Lifecycle: Not Set; Green_REACh: Incomplete
footprint Tek_131-5031-00
pins: 1, 2, 3, 4, 5

## 135-3701-201
designator J?
Connector, RF Co-ax, 50 ohm, 6GHz, Vertical, TH; Manufacturer: Cinch Connectivity; SymbolCreator: X0208326; Green_Lifecycle: Not Set; Green_REACh: Incomplete
footprint CONN_135-3701-201
pins: 1, 2, 3, 4, 5

## 135-9701-201
designator J?
Connector, MMCX,Vertical RCP 6GHz, 50Ohm, TH; Manufacturer: Cinch Connectivity; SymbolCreator: X0208326; Green_Lifecycle: Not Set; Green_REACh: Incomplete
footprint CONN_135-9701-201
pins: 1, 2, 3, 4, 5

## 142-0701-201
designator J?
Connector, SMA, TH; Manufacturer: Cinch Connectivity; SymbolCreator: X0208326; Green_Lifecycle: Not Set; Green_REACh: Incomplete
footprint Johnson_142-0701-20x
pins: 1, 2, 3, 4, 5

## 142-0701-231
designator J?
Connector, SMA, TH; Manufacturer: Cinch Connectivity; SymbolCreator: X0208326; Green_Lifecycle: Not Set; Green_REACh: Incomplete
footprint Johnson_142-0701-231
pins: 1, 2, 3, 4, 5

## 142-0701-301
designator J?
SMA Jack, 50 Ohm, Gold, R/A, TH; Manufacturer: Cinch Connectivity; SymbolCreator: a0799628; Gender: Female; Voltage_V: 335; Green_Lifecycle: Not Set; Green_REACh: Incomplete
footprint Johnson_142-0701-301
pins: 1, 2, 3, 4, 5

## 142-0701-801
designator J?
Connector, End launch SMA, 50 ohm, SMT; Manufacturer: Cinch Connectivity; SymbolCreator: X0208326; Green_Lifecycle: Not Set; Green_REACh: Incomplete
footprint JOHNSON_142-0701-801
footprint JOHNSON_142-0701-801_NoVias
pins: 1, 2, 3, 4, 5

## 142-0701-806
designator J?
Connector, End launch SMA, 50 ohm, SMT; Manufacturer: Cinch Connectivity; SymbolCreator: X0208326; Green_Lifecycle: Not Set; Green_REACh: Incomplete
footprint Johnson_142-0701-80x
footprint Johnson_142-0701-80x_NoVias
footprint Johnson_142-0701-80x_NoVias_30mil
pins: 1, 2, 3, 4, 5

## 142-0701-851
designator J?
Connector, End launch SMA, 50 ohm, SMT; Manufacturer: Cinch Connectivity; SymbolCreator: X0208326; Green_Lifecycle: Not Set; Green_REACh: Incomplete
footprint Emerson_142-0701-851
pins: 1, 2, 3, 4, 5

## 142-0701-871
designator J?
SMA, Gold, End Launch; Manufacturer: Cinch Connectivity; SymbolCreator: a0799628
footprint Emerson_142-0701-871
pins: 1, 2, 3, 4, 5

## 142-0711-201
designator J?
Connector, SMA Jack, Vertical, Gold, SMD; Manufacturer: Cinch Connectivity; SymbolCreator: a0412235; Green_Lifecycle: Not Set; Green_REACh: Incomplete
footprint 142-0711-201
pins: 1, 2

## 142-0711-821
designator J?
SMA JACK 50 OHM EDGE MNT, SMT; Manufacturer: Cinch Connectivity; SymbolCreator: X0208326; Gender: Female; ContactFinish: Gold; Green_Lifecycle: Not Set; Green_REACh: Incomplete
footprint Johnson_142-0711-821
pins: 1, 2, 3, 4, 5

## 142-0761-841
designator J?  (value not drawn)
JACK, SMA, 50 Ohm, Gold, SMT; Manufacturer: Cinch Connectivity; SymbolCreator: Altium; Gender: Female; Voltage_V: 170
footprint Johnson_142-0761-841
pins: 1, 2, 3, 4

## 142-0761-881
designator J?
Connector, End launch SMA 50 ohm, TH; Manufacturer: Cinch Connectivity; SymbolCreator: X0208326; Green_Lifecycle: Not Set; Green_REACh: Incomplete
footprint Johnson_142-0761-881
pins: 1, 2, 3, 4, 5

## 142-0771-821
designator J?
Connector, End launch SMA 50 ohm, TH; Manufacturer: Cinch Connectivity; SymbolCreator: X0208326; Green_Lifecycle: Not Set; Green_REACh: Incomplete
footprint Emerson_142-0771-821
pins: 1, 2, 3, 4, 5

## 142-0771-831
designator J?  (value not drawn)
JACK, SMA, 50 Ohm, Gold, Edge Mount; Manufacturer: Cinch Connectivity; SymbolCreator: Altium; Gender: Female; Voltage_V: 170
footprint Johnson_142-0771-831
pins: 1, 2, 3, 4

## 142-0801-801
designator J?
Connector, End launch SMA 50 ohm, SMT; Manufacturer: Cinch Connectivity; SymbolCreator: X0208326; Gender: Male; ContactFinish: Gold
footprint JOHNSON_142-0801-801
footprint JOHNSON_142-0801-801_NoVias
pins: 1, 2, 3, 4, 5

## 142-1701-831
designator J?  (value not drawn)
JACK, SMA, 50 Ohm, Gold, Edge Mount; Manufacturer: Cinch Connectivity; SymbolCreator: Altium; Gender: Female; Voltage_V: 170
footprint Johnson_142-1701-831
pins: 1, 2, 3, 4

## 172-009-202R001
designator J?
Connector, DB9, Female, Tin; Manufacturer: NorComp; SymbolCreator: a0799628; Green_Lifecycle: Not Set; Green_REACh: Incomplete
footprint Norcomp_172-009-202R001
pins: 1, 2, 3, 4, 5, 6, 7, 8, 9

## 172-015-212R911
designator J?
Receptacle, D-Sub, 15 Position, TH; Manufacturer: NorComp; SymbolCreator: Altium; Pitch_mm: 2.7686; Gender: Female; Row_Count: 2; RowSpacing_mm: 2.8448; ContactFinish: Gold; Current_A: 5; Voltage_V: 500; Cert_UL: Y
footprint Norcomp_172-015-212R911
pins: 1, 2, 3, 4, 5, 6, 7, 8, 9, 10, 11, 12, 13, 14, 15, S1, S2

## 172-037-242R911
designator J?
Receptacle, D-Sub, 37 Position, TH; Manufacturer: NorComp; SymbolCreator: Altium; Pitch_mm: 2.7686; Gender: Female; Row_Count: 2; RowSpacing_mm: 2.8448; ContactFinish: Gold; Current_A: 5; Voltage_V: 500; Cert_UL: Y
footprint Norcomp_172-037-242R911
pins: 1, 2, 3, 4, 5, 6, 7, 8, 9, 10, 11, 12, 13, 14, 15, 16, 17, 18, 19, 20, 21, 22, 23, 24, 25, 26, 27, 28, 29, 30, 31, 32, 33, 34, 35, 36, 37, S1, S2

## 172-E09-213R911
designator J?
Receptacle, D-Sub, 9 Position, TH; Manufacturer: NorComp; SymbolCreator: Altium; Pitch_mm: 2.7686; Gender: Female; Row_Count: 2; RowSpacing_mm: 2.8448; ContactFinish: Gold; Current_A: 5; Voltage_V: 500; Cert_UL: Y
footprint Norcomp_172-E09-213R911
pins: 1, 2, 3, 4, 5, 6, 7, 8, 9, S1, S2

## 172-E25-213R911
designator J?
Receptacle, D-Sub, 25 Position, TH; Manufacturer: NorComp; SymbolCreator: Altium; Pitch_mm: 2.7686; Gender: Female; Row_Count: 2; RowSpacing_mm: 2.8448; ContactFinish: Gold; Current_A: 5; Voltage_V: 500; Cert_UL: Y
footprint Norcomp_172-E25-213R911
pins: 1, 2, 3, 4, 5, 6, 7, 8, 9, 10, 11, 12, 13, 14, 15, 16, 17, 18, 19, 20, 21, 22, 23, 24, 25, S1, S2

## 180-M62-113R911
designator J?  (value not drawn)
Plug, D-Sub, 62 Pos, Gold, TH; Manufacturer: NorComp; SymbolCreator: Altium; Pitch_mm: 2.41; Gender: Male; Shrouded: Y; Row_Count: 3; Voltage_V: 1000
footprint NorComp_180-M62-113R911
pins: 1, 2, 3, 4, 5, 6, 7, 8, 9, 10, 11, 12, 13, 14, 15, 16, 17, 18, 19, 20, 21, 22, 23, 24, 25, 26, 27, 28, 29, 30, 31, 32, 33, 34, 35, 36, 37, 38, 39, 40, 41, 42, 43, 44, 45, 46, 47, 48, 49, 50, 51, 52, 53, 54, 55, 56, 57, 58, 59, 60, 61, 62, S1, S2

## 182-009-213R171
designator J?
CONN DB9 FEMALE R/A SOLDER TH; Manufacturer: NorComp; SymbolCreator: a0412235; CompType: Connector; Green_Lifecycle: Not Set; Green_REACh: Incomplete
footprint NORCOMP_182-009-213R171
pins: 1, 2, 3, 4, 5, 6, 7, 8, 9, 10, 11

## 190-009-263R001
designator J?
CONN DB9 FEMALE R/A SOLDER SMD; Manufacturer: NorComp; SymbolCreator: a07989628; CompType: Connector; Green_Lifecycle: Not Set; Green_REACh: Incomplete
footprint NORCOMP_190-009-263R001
pins: 1, 2, 3, 4, 5, 6, 7, 8, 9

## 292-04A-5
designator J?  (value not drawn)
JACK, SMA, 27 Ghz, SMT; Manufacturer: Southwest Microwave; SymbolCreator: Altium; Gender: Female
footprint SouthWest_292-04A-5
pins: 1, 2, 3, 4

## 292-07A-6
designator J?  (value not drawn)
JACK, SMA, 27 Ghz, SMT; Manufacturer: Southwest Microwave; SymbolCreator: Altium; Gender: Female; ContactFinish: Gold
footprint SouthWest_292-07A-6
pins: 1, 2, 3, 4

## 302-S101
designator J?
Header, 2.54mm, 5x2, Gold, Black, TH; Manufacturer: On-Shore Technology; SymbolCreator: a0412235; Pitch_mm: 2.54; Gender: Male; Shrouded: Y; Row_Count: 2
footprint On-Shore_302-S101
pins: 1, 2, 3, 4, 5, 6, 7, 8, 9, 10

## 302-S301
designator J?
Header(shrouded), 2.54mm, 15x2, Gold, TH; Manufacturer: On-Shore Technology; SymbolCreator: a0412235; Pitch_mm: 2.54; Gender: Male; Shrouded: Y; Row_Count: 2; Current_A: 3; Voltage_V: 250
footprint On-Shore_302-S301
pins: 1, 2, 3, 4, 5, 6, 7, 8, 9, 10, 11, 12, 13, 14, 15, 16, 17, 18, 19, 20, 21, 22, 23, 24, 25, 26, 27, 28, 29, 30

## 305-024-521-201
designator EC?  (value not drawn)  (no BOM)
Edge Connector; Manufacturer: Edac Inc.; SymbolCreator: a0799628; CompType: Card Edge Footprint; Note: PartNumber and Manufacturer are for matching connector
footprint Edge_Connector_EDAC_12x2
pins: 1, 2, 3, 4, 5, 6, 7, 8, 9, 10, 11, 12, A, B, C, D, E, F, H, J, K, L, M, N

## 307-012-500-202
designator EC?  (no BOM)
Edge Connector; Manufacturer: Edac Inc.; SymbolCreator: a0799628; CompType: Card Edge Footprint; Note: PartNumber and Manufacturer are for matching connector
footprint Edge_Connector_EDAC_6x2
pins: 1, 2, 3, 4, 5, 6, A, B, C, D, E, F

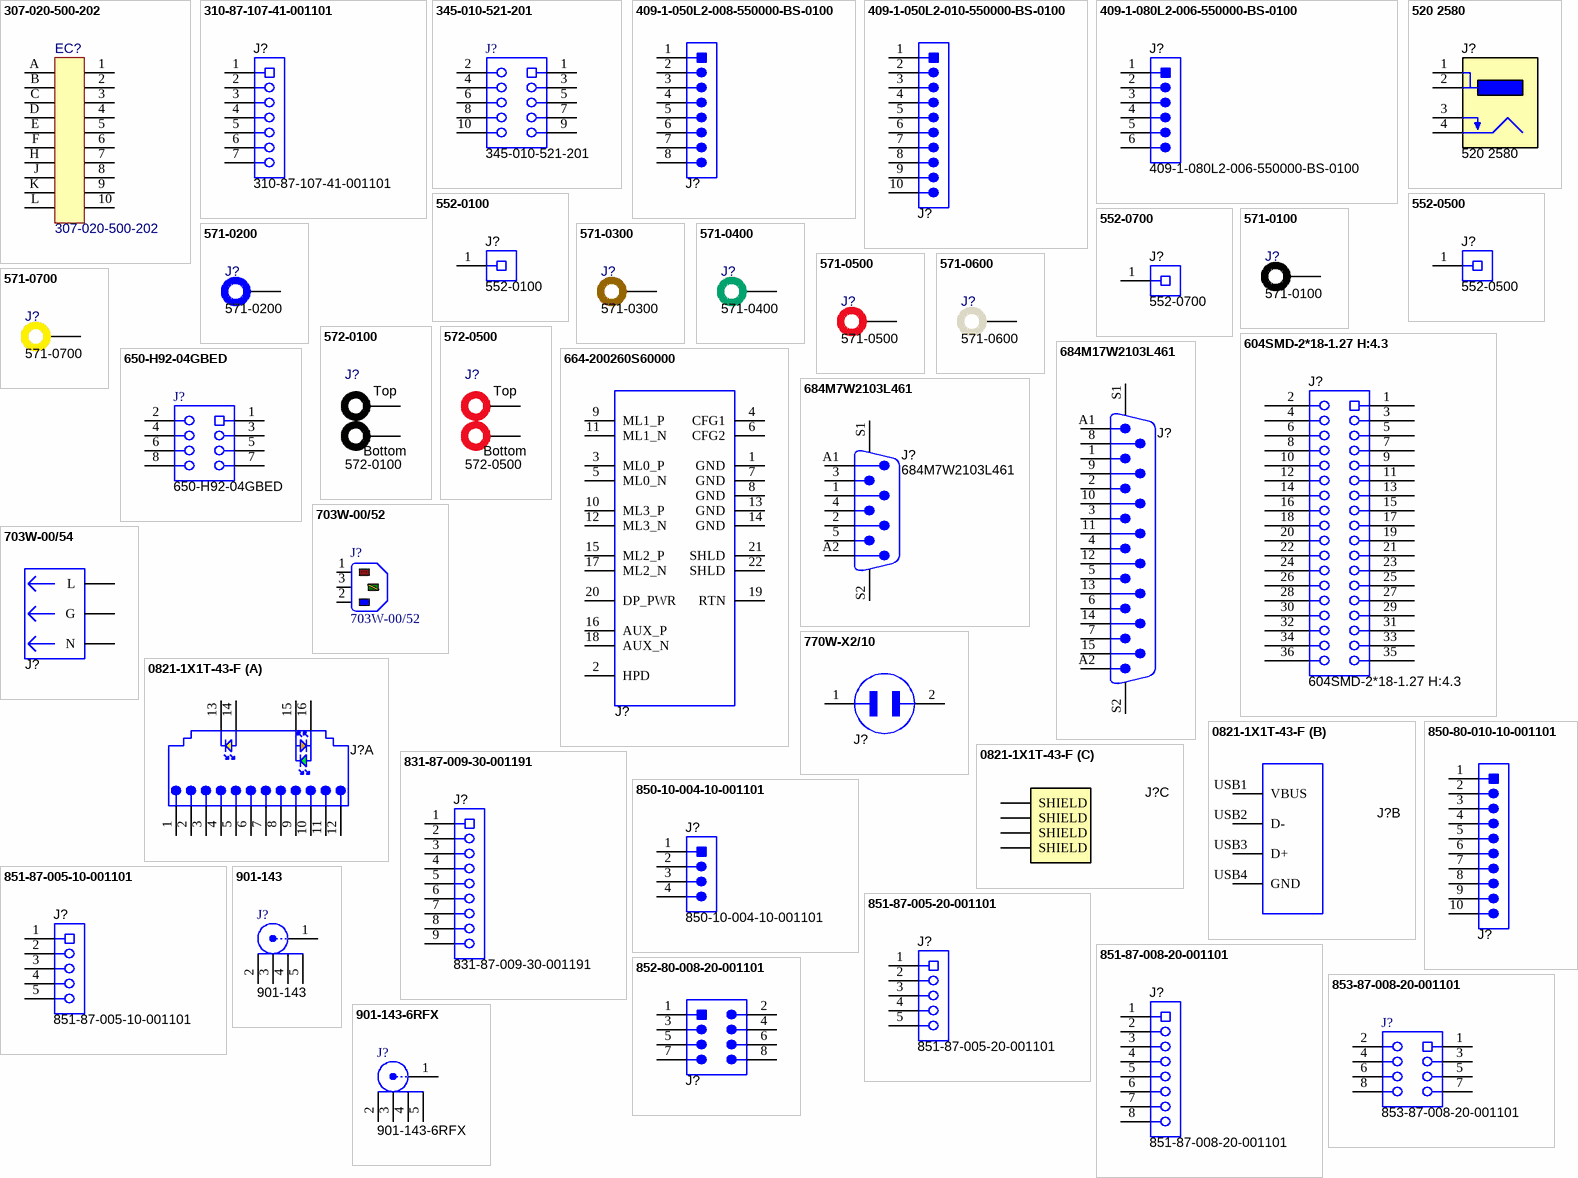
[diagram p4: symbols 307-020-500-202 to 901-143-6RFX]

## 307-020-500-202
designator EC?  (no BOM)
Edge Connector; Manufacturer: Edac Inc.; CompType: Card Edge Footprint; SymbolCreator: CADMNA/codlsc; Note: PartNumber and Manufacturer are for matching connector; U/M: EA
footprint Edge_Connector_EDAC_10x2
pins: 1, 2, 3, 4, 5, 6, 7, 8, 9, 10, A, B, C, D, E, F, H, J, K, L

## 310-87-107-41-001101
designator J?
Receptacle, 100mil, 7x1, Gold, TH; Manufacturer: Preci-Dip; SymbolCreator: Altium; Pitch_mm: 2.54; Gender: Female; Row_Count: 1
footprint Preci-dip_310-87-107-41-001101
pins: 1, 2, 3, 4, 5, 6, 7

## 345-010-521-201
designator J?
CARDEDGE 10POS DUAL .100 GREEN; Manufacturer: Edac Inc.; SymbolCreator: a0412235; CompType: Receptacle
footprint EDAC_345-010-521-201
pins: 1, 2, 3, 4, 5, 6, 7, 8, 9, 10

## 409-1-050L2-008-550000-BS-0100
designator J?  (value not drawn)
FFC & FPC Connectors .5mm 8 pad, SMT; Manufacturer: MPE-Garry GmbH; SymbolCreator: a0411947; CompType: FFC or FPC
footprint MPE_409-1-050L2-008-550000-BS-0100
pins: 1, 2, 3, 4, 5, 6, 7, 8

## 409-1-050L2-010-550000-BS-0100
designator J?  (value not drawn)
FFC & FPC Connectors .5mm 10 pad, SMT; Manufacturer: MPE-Garry GmbH; SymbolCreator: a0412235; CompType: FFC or FPC
footprint MPE_409-1-050L2-010-550000-BS-0100
pins: 1, 2, 3, 4, 5, 6, 7, 8, 9, 10

## 409-1-080L2-006-550000-BS-0100
designator J?
FFC & FPC Connectors .8mm 6 pad, SMT; Manufacturer: MPE-Garry GmbH; SymbolCreator: a0412235; CompType: FFC or FPC
footprint MPE_409-1-080L2-006-550000-BS-0100
pins: 1, 2, 3, 4, 5, 6

## 520 2580
designator J?
DC socket, 4Pos, TH; Manufacturer: ROKA Berlin; SymbolCreator: x0208325
footprint ROKA_520_2580
pins: 1, 2, 3, 4

## 552-0100
designator J?
4mm Single Pole Connector, Brass, Black, TH; Manufacturer: DEM Manufacturing; SymbolCreator: a0799628; CompType: Pin Receptacle; Gender: Female; Current_A: 16; Voltage_V: 50
footprint Dem_552-0100
pins: 1

## 552-0500
designator J?
4mm Single Pole Connector, Brass, Red, TH; Manufacturer: DEM Manufacturing; SymbolCreator: a0799628; CompType: Pin Receptacle; Gender: Female; Current_A: 16; Voltage_V: 50
footprint Dem_552-0500
pins: 1

## 552-0700
designator J?
4mm Single Pole Connector, Brass, Yellow, TH; Manufacturer: DEM Manufacturing; SymbolCreator: a0799628; CompType: Pin Receptacle; Gender: Female; Current_A: 16; Voltage_V: 50
footprint Dem_552-0700
pins: 1

## 571-0100
designator J?
Standard Banana Jack, insulated, 10A, black; Manufacturer: DEM Manufacturing; SymbolCreator: codlsc; U/M: EA; Green_Lifecycle: Not Set; Green_REACh: Incomplete
footprint 571-0100
footprint 571-0100_handsolder
pins: 1, 2

## 571-0200
designator J?
Standard Banana Jack, insulated, 10A, blue; Manufacturer: DEM Manufacturing; SymbolCreator: codlsc; U/M: EA
footprint 571-0200
footprint 571-0200_handsolder
pins: 1, 2

## 571-0300
designator J?
Standard Banana Jack, insulated, 10A, brown; Manufacturer: DEM Manufacturing
footprint 571-0300
footprint 571-0300_handsolder
pins: 1, 2

## 571-0400
designator J?
Standard Banana Jack, insulated, 10A, green; Manufacturer: DEM Manufacturing; SymbolCreator: codlsc; U/M: EA
footprint 571-0400
footprint 571-0400_handsolder
pins: 1, 2

## 571-0500
designator J?
Standard Banana Jack, insulated, 10A, red; Manufacturer: DEM Manufacturing; SymbolCreator: codlsc; U/M: EA; Green_Lifecycle: Not Set; Green_REACh: Incomplete
footprint 571-0500
footprint 571-0500_handsolder
pins: 1, 2

## 571-0600
designator J?
Standard Banana Jack, insulated, 10A, white; Manufacturer: DEM Manufacturing
footprint 571-0600
footprint 571-0600_handsolder
pins: 1, 2

## 571-0700
designator J?
Standard Banana Jack, insulated, 10A, yellow; Manufacturer: DEM Manufacturing; Green_Lifecycle: Not Set; Green_REACh: Incomplete
footprint 571-0700
footprint 571-0700_handsolder
pins: 1, 2

## 572-0100
designator J?
Standard Banana Jack, insulated, 10A, dual black; Manufacturer: DEM Manufacturing; SymbolCreator: codlsc; U/M: EA
footprint 164-6220
footprint 164-6220_handsolder
pins: 1, 2, 3

## 572-0500
designator J?
Standard Banana Jack, insulated, 10A, dual red; Manufacturer: DEM Manufacturing; SymbolCreator: codlsc; U/M: EA
footprint 164-6221
footprint 164-6221_handsolder
pins: 1, 2, 3

## 604SMD-2*18-1.27 H:4.3
designator J?
Receptacle, 1.27mm, 18x2, Gold, SMT; Manufacturer: Yangzhan Electronic; SymbolCreator: a0411947; Pitch_mm: 1.27; Gender: Female; Row_Count: 2; Current_A: 1; Voltage_V: 500; Cert_UL: Y
footprint YZCONN_604SMD-2_18
pins: 1, 2, 3, 4, 5, 6, 7, 8, 9, 10, 11, 12, 13, 14, 15, 16, 17, 18, 19, 20, 21, 22, 23, 24, 25, 26, 27, 28, 29, 30, 31, 32, 33, 34, 35, 36

## 650-H92-04GBED
designator J?
Receptacle, 1mm, 4x2, Gold, SMT; Manufacturer: PINREX TECHNOLOGY CORP; SymbolCreator: a0412235
footprint PT_650-H92-04GBED
pins: 1, 2, 3, 4, 5, 6, 7, 8

## 664-200260S60000
designator J?  (value not drawn)
Mini DisplayPort Connector, 0.6 mm, 10x2, Gold, Black, SMT/TH; Manufacturer: Bizlink; SymbolCreator: Altium; Pitch_mm: 0.6; Gender: Female; Shrouded: Y; Row_Count: 2; Green_Lifecycle: Not Set; Green_REACh: Incomplete
footprint BizLink_664-200260S60000
pins: 1 GND, 2 HPD, 3 ML0_P, 4 CFG1, 5 ML0_N, 6 CFG2, 7 GND, 8 GND, 9 ML1_P, 10 ML3_P, 11 ML1_N, 12 ML3_N, 13 GND, 14 GND, 15 ML2_P, 16 AUX_P, 17 ML2_N, 18 AUX_N, 19 RTN, 20 DP_PWR, 21 SHLD, 22 SHLD

## 684M7W2103L461
designator J?
D-SUB CONN, 7 Pins, Gold, Black, R/A, TH; Manufacturer: NorComp; SymbolCreator: Altium; Pitch_mm: 2.77; Gender: Male; Shrouded: Y; Current_A: 40
footprint Norcomp_684M7W2103L461
pins: 1, 2, 3, 4, 5, A1, A2, S1, S2

## 684M17W2103L461
designator J?  (value not drawn)
D-SUB CONN, 17 Pins, Gold, R/A, TH; Manufacturer: NorComp; SymbolCreator: Altium; Pitch_mm: 2.77; Gender: Male; Shrouded: Y; Current_A: 40
footprint NorComp_684M17W2103L461
pins: 1, 2, 3, 4, 5, 6, 7, 8, 9, 10, 11, 12, 13, 14, 15, A1, A2, S1, S2

## 703W-00/52
designator J?
IEC Connector, 10A, 250V, R/A, TH; Manufacturer: Qualtek Electronics Corporation; SymbolCreator: Altium; CompType: Socket; Pitch_mm: 7; Gender: Male; Row_Count: 1
footprint Qualtek_703W-00_52
pins: 1 L (power) "Live (Active)", 2 N (power) "Neutral", 3 E (power) "Earth (Ground)"

## 703W-00/54
designator J?  (value not drawn)
AC Receptacle, 10A 250VAC; Manufacturer: Qualtek Electronics Corporation; SymbolCreator: a0799628; CompType: Connector; Green_Lifecycle: Not Set; Green_REACh: Incomplete
footprint CONN_QUALTEK-703W-0054
pins: 1 L, 2 N, 3 G

## 770W-X2/10
designator J?  (value not drawn)
AC Receptacle, 2.5A, R/A, TH; Manufacturer: Qualtek Electronics Corporation; SymbolCreator: a0412235; Green_Lifecycle: Not Set; Green_REACh: Incomplete
footprint CONN_AC_770W-SERIES
pins: 1 Neutral, 2 Hot

## 0821-1X1T-43-F
designator J?  (value not drawn)
Connector, MadJack, USB Type A, R/A, TH; Manufacturer: Bel Fuse; SymbolCreator: Altium; Gender: Female; ContactFinish: Gold; Voltage_V: 750; Cert_UL: Y
footprint Bel_0821-1X1T-43-F
part A pins: 1 TRCT3, 2 TRD3-, 3 TRD3+, 4 TRD2+, 5 TRD2-, 6 TRCT2, 7 TRCT4, 8 TRD4+, 9 TRD4-, 10 TRD1-, 11 TRD1+, 12 TRCT1, 13 K1, 14 A1, 15, 16
part B pins: USB1 VBUS "+5V", USB2 D- "Data -", USB3 D+ "Data +", USB4 GND "Ground"
part C pins: MH1 SHIELD, MH2 SHIELD, MH3 SHIELD, MH4 SHIELD

## 831-87-009-30-001191
designator J?
Receptacle, 2mm, 9x1, Gold, SMT; Manufacturer: Preci-Dip; SymbolCreator: x0208325; Pitch_mm: 2; Gender: Female; Row_Count: 1; Current_A: 3; Cert_UL: Y
footprint Preci-dip_831-87-009-30-001101
pins: 1, 2, 3, 4, 5, 6, 7, 8, 9

## 850-10-004-10-001101
designator J?
Header, 50mil, 4x1, Gold, TH; Manufacturer: Preci-Dip; SymbolCreator: a0412235
footprint Preci-dip_850-xx-004-10-001101
pins: 1, 2, 3, 4

## 850-80-010-10-001101
designator J?  (value not drawn)
Header, 50mil, 10x1, Tin, TH; Manufacturer: Preci-Dip; SymbolCreator: a0412235
footprint PRECI-DIP_850-80-010-10-001101
pins: 1, 2, 3, 4, 5, 6, 7, 8, 9, 10

## 851-87-005-10-001101
designator J?
Receptacle, 5x1, 1.27mm, TH; Manufacturer: Preci-Dip; SymbolCreator: a0412235; CompType: Socket
footprint PRECI-DIP_851-87-005-10-001101
pins: 1, 2, 3, 4, 5

## 851-87-005-20-001101
designator J?
Receptacle, 50mil, 5x1, Gold, R/A, TH; Manufacturer: Preci-Dip; SymbolCreator: a0412235
footprint Preci-dip_851-87-005-20-001101
pins: 1, 2, 3, 4, 5

## 851-87-008-20-001101
designator J?
Receptacle, 50mil, 8x1, Gold, R/A, TH; Manufacturer: Preci-Dip; SymbolCreator: a0411947
footprint Preci-dip_851-87-008-20-001101
pins: 1, 2, 3, 4, 5, 6, 7, 8

## 852-80-008-20-001101
designator J?  (value not drawn)
Header, 50mil, 4x2, R/A, TH; Manufacturer: Preci-Dip; SymbolCreator: a0411947
footprint Preci-dip_852-xx-008-20-001101
pins: 1, 2, 3, 4, 5, 6, 7, 8

## 853-87-008-20-001101
designator J?
Receptacle, 50mil, 4x2, Gold, R/A, TH; Manufacturer: Preci-Dip; SymbolCreator: a0412235
footprint Preci-dip_853-xx-008-20-001101
pins: 1, 2, 3, 4, 5, 6, 7, 8

## 901-143
designator J?
Connector, Right Angle SMA 50 ohm, TH; Manufacturer: Amphenol RF; SymbolCreator: X0208326; Green_Lifecycle: Not Set; Green_REACh: Incomplete
footprint Amphenol_901-143
pins: 1, 2, 3, 4, 5

## 901-143-6RFX
designator J?
JACK, SMA, 50 Ohm, Gold, R/A, TH; Manufacturer: Amphenol RF; SymbolCreator: X0208326; Gender: Female
footprint Amphenol_901-143-6RFX
pins: 1, 2, 3, 4, 5

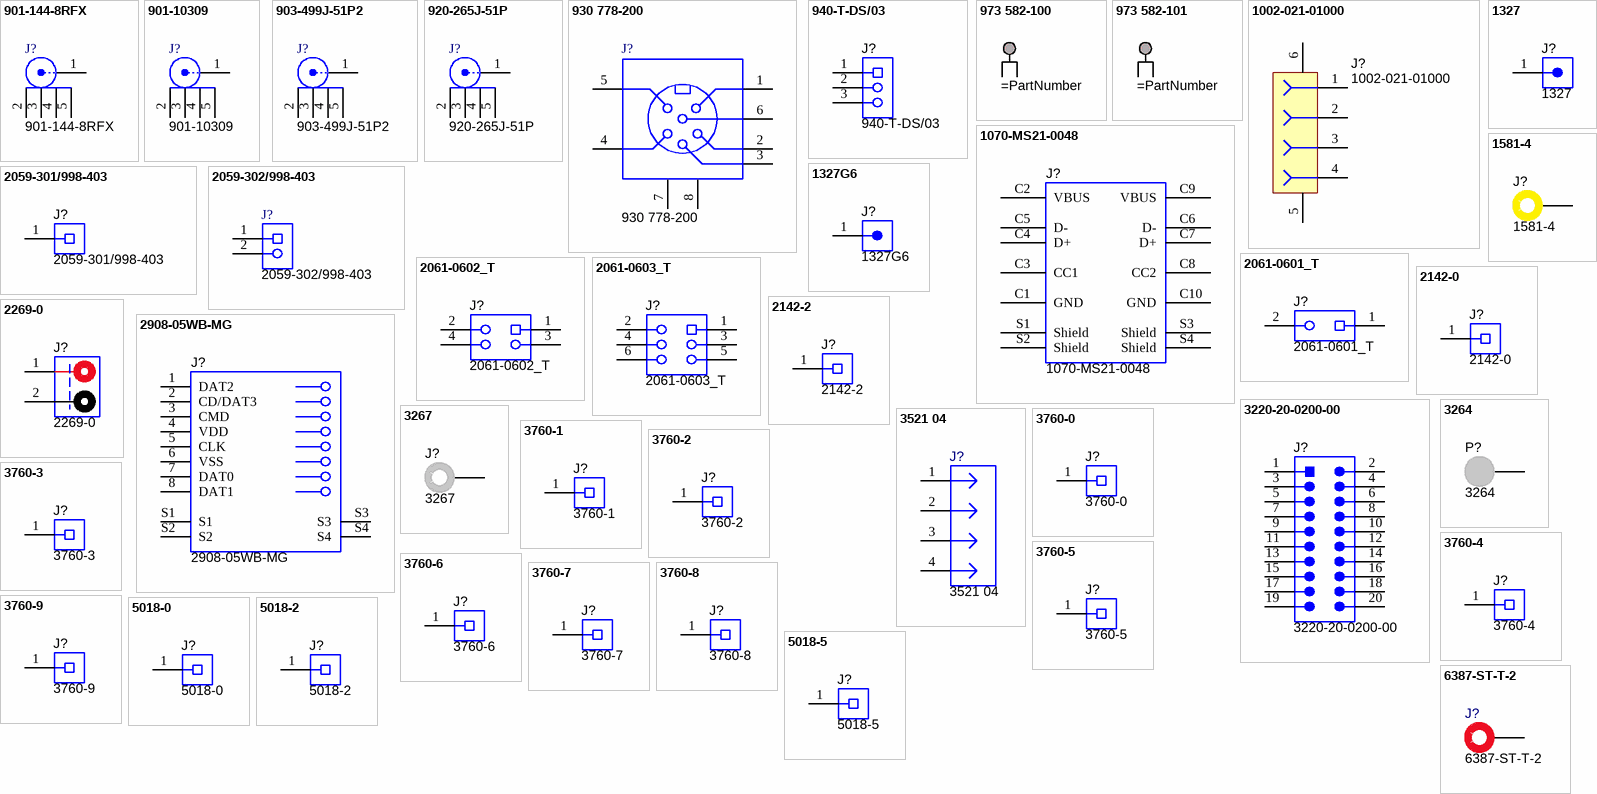
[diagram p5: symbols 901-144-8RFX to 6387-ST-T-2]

## 901-144-8RFX
designator J?
SMA Straight Jack, Gold, 50 Ohm, TH; Manufacturer: Amphenol RF; SymbolCreator: X0208326; Green_Lifecycle: Not Set; Green_REACh: Incomplete
footprint Amphenol_901-144-8RFX
pins: 1, 2, 3, 4, 5

## 901-10309
designator J?
SMA JACK 50 OHM EDGE MNT, SMT; Manufacturer: Amphenol-Tuchel Electronics; SymbolCreator: X0208326; ContactFinish: Gold
footprint Amphenol_901-10309
pins: 1, 2, 3, 4, 5

## 903-499J-51P2
designator J?
JACK, SMB 50 Ohm, TH; Manufacturer: Amphenol RF; SymbolCreator: X0208326; Gender: Male; ContactFinish: Gold
footprint Amphenol_903-499J-51P2
pins: 1, 2, 3, 4, 5

## 920-265J-51P
designator J?
Jack, Straight, 50 Ohm, Gold, TH; Manufacturer: Amphenol RF; SymbolCreator: X0208326; Gender: Female
footprint Amphenol_920-265J-51P
pins: 1, 2, 3, 4, 5

## 930 778-200
designator J?
Connector, DIN, 6pin, TH; Manufacturer: Hirschmann; SymbolCreator: x0208326; CompType: Socket
footprint Hirschmann_930 778-200
pins: 1, 2, 3  , 4  , 5  , 6  , 7   (power), 8   (power)

## 940-T-DS/03
designator J?
Terminal Block, 5.08mm, 3x1, Tin, TH; Manufacturer: WECO; SymbolCreator: a0412235
footprint WECO_940-T-DS-03
pins: 1, 2, 3

## 973 582-100
designator =PartNumber, comment TESTPOINT_2Pos  (value not drawn)
TEST SOCKET, PCB, 4MM, BLACK; PartNumber: 973 582-100; Manufacturer: Hirschmann; SymbolCreator: a0799628; CompType: Banana Jack
footprint HIRSCHMANN_973 582-100
pins: 1, 2

## 973 582-101
designator =PartNumber, comment TESTPOINT_2Pos  (value not drawn)
TEST SOCKET, PCB, 4MM, RED; PartNumber: 973 582-101; Manufacturer: Hirschmann; SymbolCreator: a0799628; CompType: Banana Jack
footprint HIRSCHMANN_973 582-101
pins: 1, 2

## 1002-021-01000
designator J?
Connector, Receptable, USB Type A, Vertical, TH; Manufacturer: CnC Tech; SymbolCreator: a0412235; Gender: Female; Green_Lifecycle: Not Set; Green_REACh: Incomplete
footprint CONN_1002-021-01000
pins: 1, 2, 3, 4, 5, 6

## 1070-MS21-0048
designator J?
Connector, Receptacle, USB Type C, 10 Pins, R/A, SMT; Manufacturer: Speedtech; SymbolCreator: Altium; Gender: Female; Row_Count: 1; ContactFinish: Gold
footprint Speedtech_1070-MS21-0048
pins: C1 GND, C2 VBUS, C3 CC1, C4 D+, C5 D-, C6 D-, C7 D+, C8 CC2, C9 VBUS, C10 GND, S1 Shield, S2 Shield, S3 Shield, S4 Shield

## 1327
designator J?
Heavy Duty Power Connectors, HOUSING ONLY, Red; Manufacturer: Anderson Power Products; SymbolCreator: a0412235; Note: Need to specify 1335G1 terminal contact
footprint APP_1327
pins: 1

## 1327G6
designator J?
Heavy Duty Power Connectors, HOUSING ONLY, Black; Manufacturer: Anderson Power Products; SymbolCreator: a0412235; Note: Need to specify 1335G1 terminal contact
footprint APP_1327G6
pins: 1

## 1581-4
designator J?
Banana Jack, Yellow, TH; Manufacturer: Pomona Electronics; SymbolCreator: a0799721; Gender: Female; ContactFinish: Tin; Current_A: 15
footprint Pomona_1581-4
pins: 1

## 2059-301/998-403
designator J?
Terminal Block, 1-pole, Tin, SMD; Manufacturer: WAGO; SymbolCreator: a0799628; Gender: Female; Current_A: 3; Voltage_V: 160
footprint WAGO_2059-301
pins: 1

## 2059-302/998-403
designator J?
Terminal Block, 3mm, 2-pole, Tin, SMD; Manufacturer: WAGO; SymbolCreator: a0412235; Pitch_mm: 3; Gender: Female
footprint WAGO_2059-302
pins: 1, 2

## 2061-0601_T
designator J?
Terminal Block with Pushbutton, 1-pole, Height 5.6mm, SMD; Manufacturer: WAGO; SymbolCreator: Altium
footprint WAGO_2061-0601_T
pins: 1, 2

## 2061-0602_T
designator J?
Terminal Block with Pushbutton, 2-pole, Height 5.6mm, SMD; Manufacturer: WAGO; SymbolCreator: a0411947
footprint WAGO_2061-0602_T
pins: 1, 2, 3, 4

## 2061-0603_T
designator J?
Terminal Block with Pushbutton, 3-pole, Height 5.6mm, SMD; Manufacturer: WAGO; SymbolCreator: Altium
footprint WAGO_2061-0603_T
pins: 1, 2, 3, 4, 5, 6

## 2142-0
designator J?
Banana Jack 0.100" Plugs, Black, TH; Manufacturer: Pomona Electronics; SymbolCreator: a0799628
footprint Pomona_2142-0
pins: 1

## 2142-2
designator J?
Banana Jack 0.100" Plugs, Red, TH; Manufacturer: Pomona Electronics; SymbolCreator: a0799628
footprint Pomona_2142-2
pins: 1

## 2269-0
designator J?
Connector, Banana Jack, Double, Black Base, 15A, TH; Manufacturer: Pomona Electronics; SymbolCreator: a0799721
footprint CONN_POMONA_2269-0
pins: 1, 2

## 2908-05WB-MG
designator J?
Connector, Micro SD, R/A, SMD; Manufacturer: 3M; SymbolCreator: Altium; Pitch_mm: 1.1; Gender: Female; Row_Count: 1; ContactFinish: Gold
footprint 3M_2908-05WB-MG
pins: 1 DAT2, 2 CD/DAT3, 3 CMD, 4 VDD, 5 CLK, 6 VSS, 7 DAT0, 8 DAT1, S1, S2, S3, S4

## 3220-20-0200-00
designator J?
Header (Shrouded), 1.27mm, 10x2, Gold, R/A, TH; Manufacturer: CnC Tech; SymbolCreator: a0412235; Pitch_mm: 1.27; Gender: Male; Shrouded: Y; Row_Count: 2; Current_A: 1; Voltage_V: 500
footprint CnC_3220-20-0200-00
pins: 1, 2, 3, 4, 5, 6, 7, 8, 9, 10, 11, 12, 13, 14, 15, 16, 17, 18, 19, 20

## 3264
designator P?
Banana Plug Connector Standard Banana Threaded, External (Nut); Manufacturer: Pomona Electronics; SymbolCreator: Altium; CompType: Banana Jack; Gender: Male; Shrouded: N; ContactFinish: Nickel; Current_A: 15; Voltage_V: 5000
footprint Pomona_3264
pins: 1

## 3267
designator J?
Standard Banana Jack, Uninsulated; Manufacturer: Pomona Electronics; SymbolCreator: a0412235; Green_Lifecycle: Not Set; Green_REACh: Incomplete
footprint Pomona_3267
pins: 1

## 3521 04
designator J?  (no BOM)
Connector, Card Edge 4x2, 2.5mm Pitch; Manufacturer: Lumberg; SymbolCreator: a0412235; CompType: Card Edge Footprint; Note: PartNumber and Manufacturer are for matching connector
footprint EDGE_CONN_RAST25-4
pins: 1, 2, 3, 4

## 3760-0
designator J?
Binding Post, Bright Tin, Black, TH; Manufacturer: Pomona Electronics; SymbolCreator: a0799628; CompType: Receptacle; Green_Lifecycle: Not Set; Green_REACh: Incomplete
footprint Pomona_3760-0
pins: 1

## 3760-1
designator J?
Binding Post, Bright Tin, Brown, TH; Manufacturer: Pomona Electronics; SymbolCreator: a0799628; CompType: Receptacle; Current_A: 15
footprint Pomona_3760-1
pins: 1

## 3760-2
designator J?
Binding Post, Bright Tin, Red, TH; Manufacturer: Pomona Electronics; SymbolCreator: a0799628; CompType: Receptacle; Green_Lifecycle: Not Set; Green_REACh: Incomplete
footprint Pomona_3760-2
pins: 1

## 3760-3
designator J?
Binding Post, Bright Tin, Orange, TH; Manufacturer: Pomona Electronics; SymbolCreator: a0799628; CompType: Receptacle
footprint Pomona_3760-3
pins: 1

## 3760-4
designator J?
Binding Post, Bright Tin, Yellow, TH; Manufacturer: Pomona Electronics; SymbolCreator: a0799628; CompType: Receptacle
footprint Pomona_3760-4
pins: 1

## 3760-5
designator J?
Binding Post, Bright Tin, Green, TH; Manufacturer: Pomona Electronics; SymbolCreator: a0799628; CompType: Receptacle; Green_Lifecycle: Not Set; Green_REACh: Incomplete
footprint Pomona_3760-5
pins: 1

## 3760-6
designator J?
Binding Post, Bright Tin, Blue, TH; Manufacturer: Pomona Electronics; SymbolCreator: a0799628; CompType: Receptacle
footprint Pomona_3760-6
pins: 1

## 3760-7
designator J?
Binding Post, Bright Tin, Violet, TH; Manufacturer: Pomona Electronics; SymbolCreator: a0799628; CompType: Receptacle; Current_A: 15
footprint Pomona_3760-7
pins: 1

## 3760-8
designator J?
Binding Post, Bright Tin, Gray, TH; Manufacturer: Pomona Electronics; SymbolCreator: a0799628; CompType: Receptacle
footprint Pomona_3760-8
pins: 1

## 3760-9
designator J?
Binding Post, Bright Tin, White, TH; Manufacturer: Pomona Electronics; SymbolCreator: a0799628; CompType: Receptacle
footprint Pomona_3760-9
pins: 1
